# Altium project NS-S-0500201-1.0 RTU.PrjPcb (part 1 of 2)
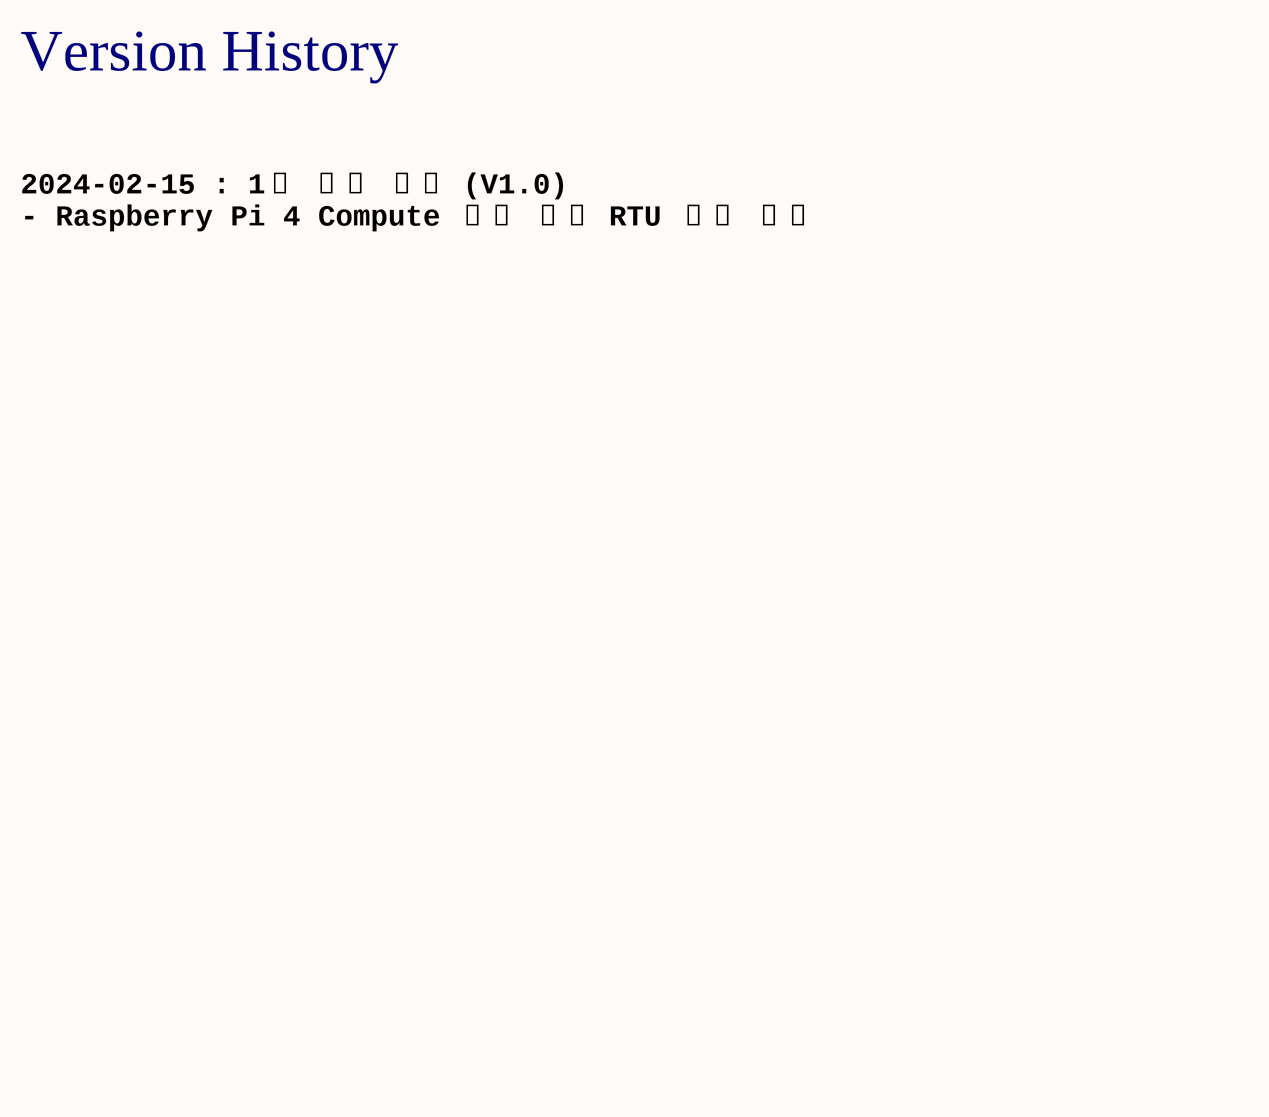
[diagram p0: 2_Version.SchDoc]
approved: 박건우(PARK K.W.); checked: 김정우(KIM J.W.); department: 전력기술팀; draw: 박진우(PARK J.W.); model: NS-S-0500201-1.0 RTU; project: Raspberry Pi 4 Compute 모듈 기반 RTU; size: A3; status: 검토중; version: 1.0
10 sheets, 268 parts. Net scope: flat (ports and power ports of the same name join across sheets).
Board file: NS-S-0500201-1.0 RTU.PcbDoc
Sheets:
  1_Cover.SchDoc
  2_Version.SchDoc
  3_Power_Boot.SchDoc
  4_CM4_CONN.SchDoc
  5_PERIPHERALS.SchDoc
  6_USB2.0.SchDoc
  7_USB3.0.SchDoc
  8_CANFD.SchDoc
  9_RS485.SchDoc
  10_HW_Component.SchDoc

## Sheet 1_Cover.SchDoc
size A3; SheetNumber: 1; SheetTotal: 9

## Sheet 2_Version.SchDoc
size A3; SheetNumber: 2; SheetTotal: 9

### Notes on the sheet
- Version History
- 2024-02-15 : 1차 회로 설계 (V1.0)
  - Raspberry Pi 4 Compute 모듈 기반 RTU 설계 초안

## Sheet 3_Power_Boot.SchDoc
size A3; SheetNumber: 3; SheetTotal: 8
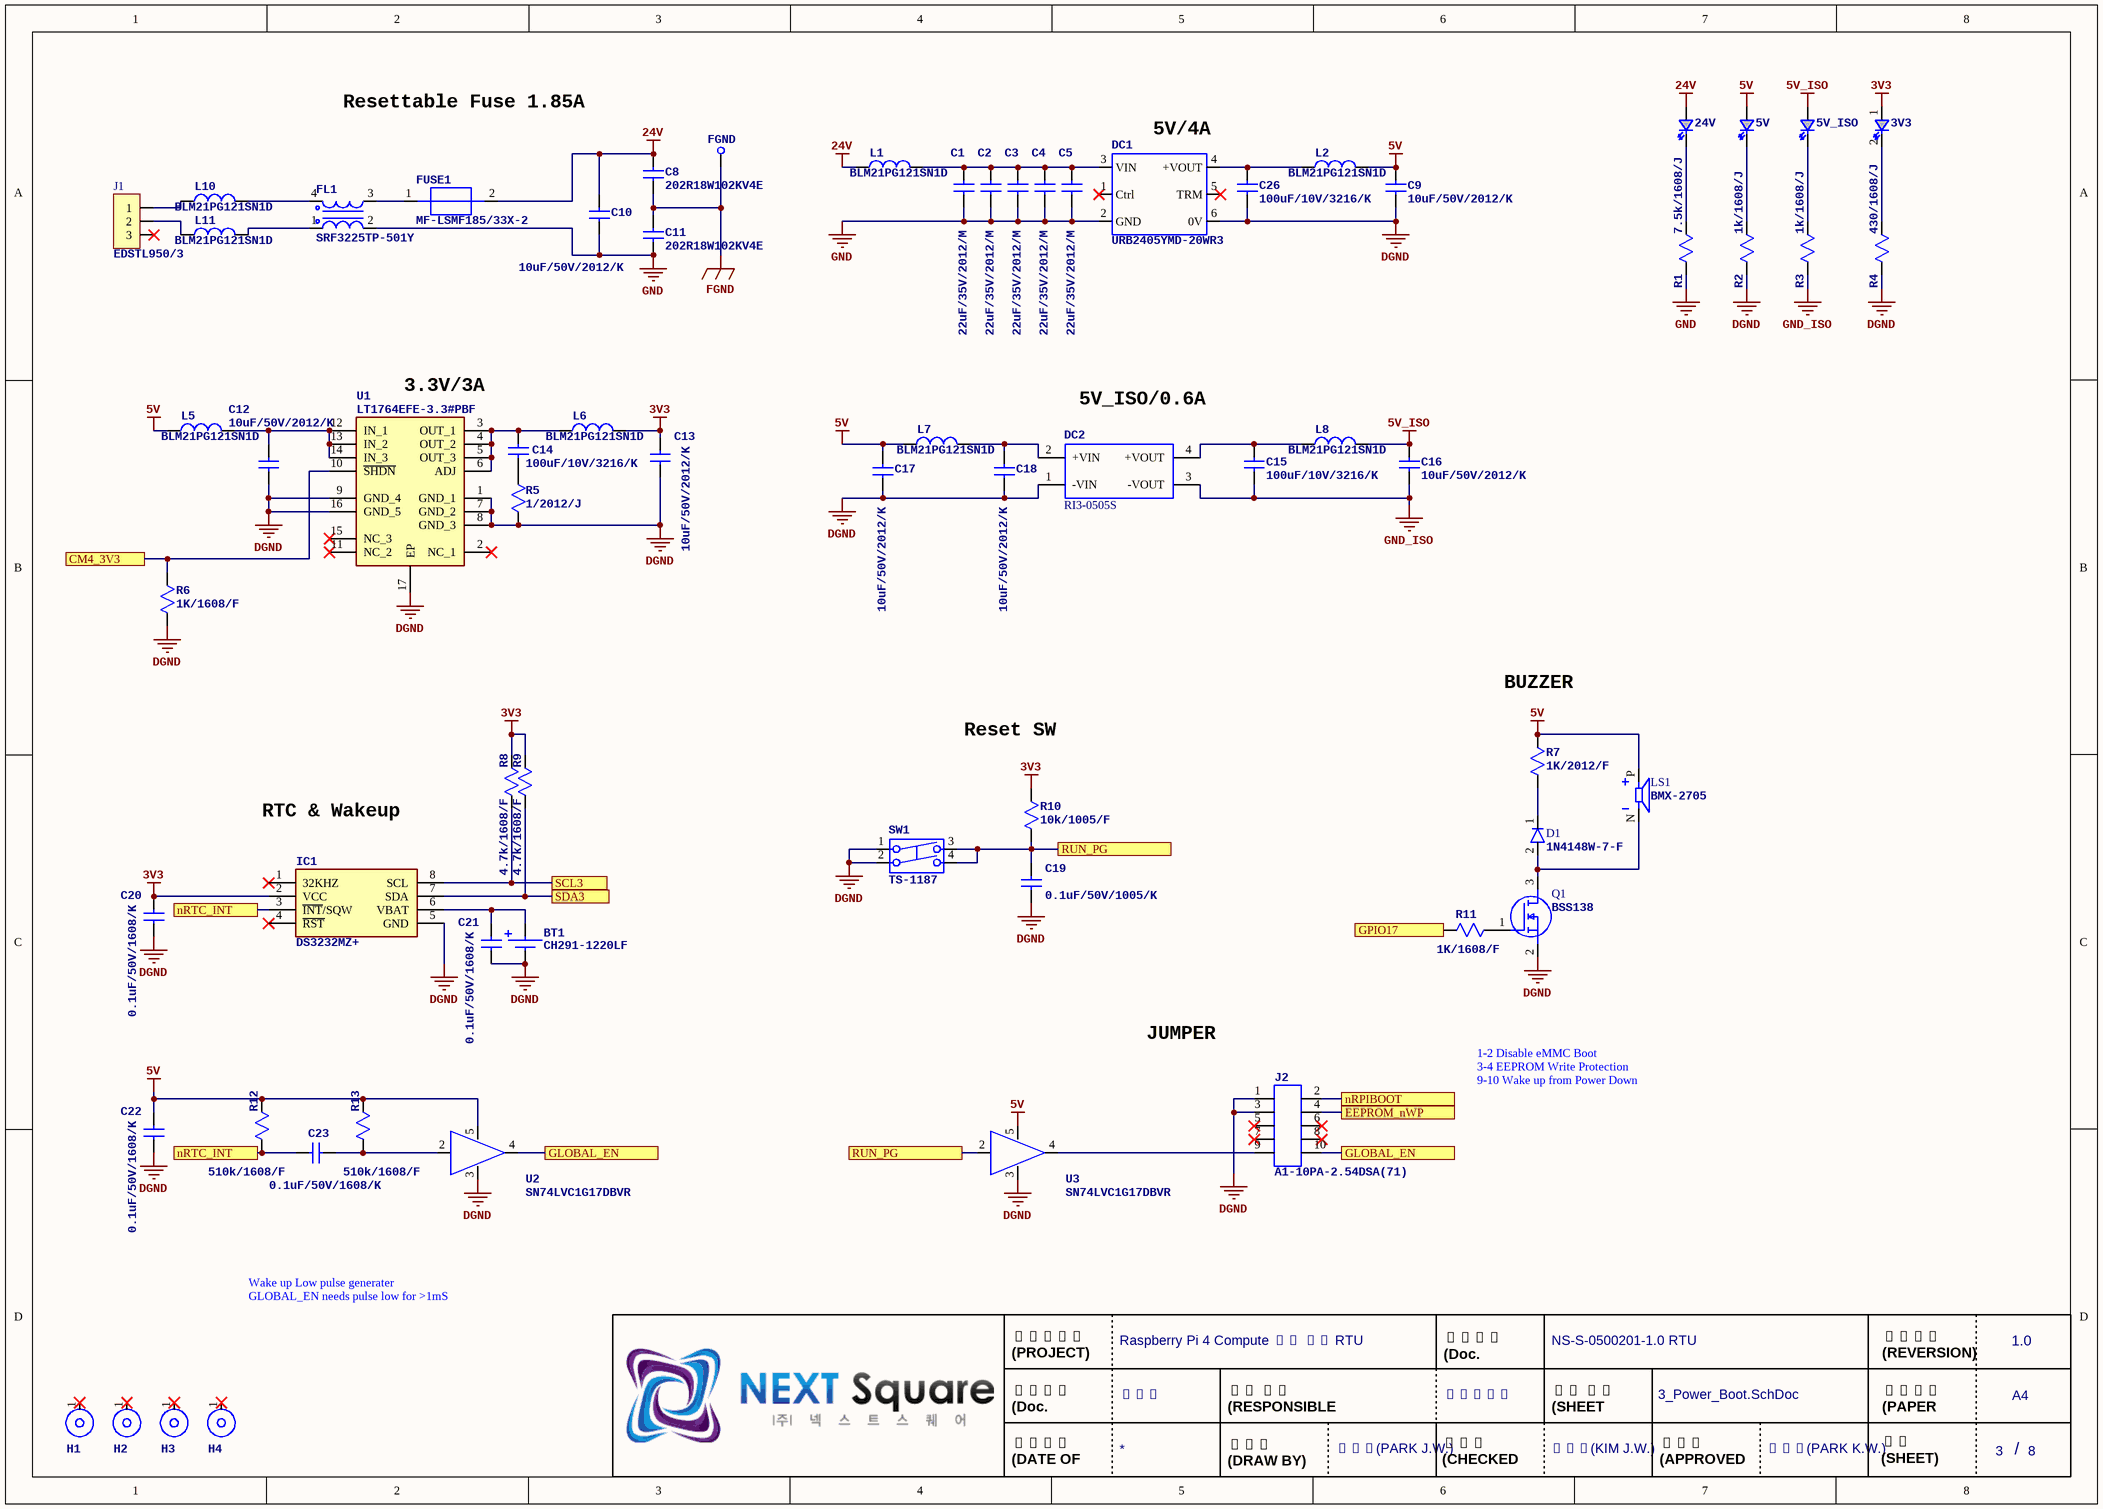
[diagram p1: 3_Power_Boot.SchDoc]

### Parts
3V3  LED Green[1608]  [LED1608]  (value not drawn)
5V  LED Green[1608]  [LED1608]  (value not drawn)
5V_ISO  LED Green[1608]  [LED1608]  (value not drawn)
24V  LED Green[1608]  [LED1608]  (value not drawn)
BT1  CH291-1220LF  [CH291-1220LF]
C1  value 22uF/35V/2012/M  [C2012]  (hidden comment: C [2012])
C2  value 22uF/35V/2012/M  [C2012]  (hidden comment: C [2012])
C3  value 22uF/35V/2012/M  [C2012]  (hidden comment: C [2012])
C4  value 22uF/35V/2012/M  [C2012]  (hidden comment: C [2012])
C5  value 22uF/35V/2012/M  [C2012]  (hidden comment: C [2012])
C8  202R18W102KV4E  [C3216]
C9  value 10uF/50V/2012/K  [C2012]  (hidden comment: C [2012])
C10  value 10uF/50V/2012/K  [C2012]  (hidden comment: C [2012])
C11  202R18W102KV4E  [C3216]
C12  value 10uF/50V/2012/K  [C2012]  (hidden comment: C [2012])
C13  value 10uF/50V/2012/K  [C2012]  (hidden comment: C [2012])
C14  value 100uF/10V/3216/K  [C3216]  (hidden comment: C [3216])
C15  value 100uF/10V/3216/K  [C3216]  (hidden comment: C [3216])
C16  value 10uF/50V/2012/K  [C2012]  (hidden comment: C [2012])
C17  value 10uF/50V/2012/K  [C2012]  (hidden comment: C [2012])
C18  value 10uF/50V/2012/K  [C2012]  (hidden comment: C [2012])
C19  value 0.1uF/50V/1005/K  [C1005]  (hidden comment: C [1005])  (no BOM)
C20  value 0.1uF/50V/1608/K  [C1608]  (hidden comment: C [1608])
C21  value 0.1uF/50V/1608/K  [C1608]  (hidden comment: C [1608])
C22  value 0.1uF/50V/1608/K  [C1608]  (hidden comment: C [1608])
C23  value 0.1uF/50V/1608/K  [C1608]  (hidden comment: C [1608])
C26  value 100uF/10V/3216/K  [C3216]  (hidden comment: C [3216])
D1  1N4148W-7-F  [SOD-123]
DC1  URB2405YMD-20WR3  [URB2405YMD-20WR3]
DC2  RI3-0505S  [RI3-0505S]
FGND  TP  [ST-1-1]  (value not drawn)
FL1  SRF3225TP-501Y  [SRF3225TP-501Y]
FUSE1  MF-LSMF185/33X-2  [MF-LSMF185_33X-2]
H1  HOLE_(3/6)  [NTH_3.6]  (value not drawn)
H2  HOLE_(3/6)  [NTH_3.6]  (value not drawn)
H3  HOLE_(3/6)  [NTH_3.6]  (value not drawn)
H4  HOLE_(3/6)  [NTH_3.6]  (value not drawn)
IC1  DS3232MZ+  [SOIC8_1.27_6.0]
J1  EDSTL950/3  [EDSTL950_3]
J2  A1-10PA-2.54DSA(71)  [A1-10PA-2.54DSA]
L1  BLM21PG121SN1D  [L2012]
L2  BLM21PG121SN1D  [L2012]
L5  BLM21PG121SN1D  [L2012]
L6  BLM21PG121SN1D  [L2012]
L7  BLM21PG121SN1D  [L2012]
L8  BLM21PG121SN1D  [L2012]
L10  BLM21PG121SN1D  [L2012]
L11  BLM21PG121SN1D  [L2012]
LS1  BMX-2705  [BUZZER-BMX-2705]
Q1  BSS138  [SOT23L]
R1  value 7.5k/1608/J  [R1608]  (hidden comment: R [1608]_J)
R2  value 1k/1608/J  [R1608]  (hidden comment: R [1608]_J)
R3  value 1k/1608/J  [R1608]  (hidden comment: R [1608]_J)
R4  value 430/1608/J  [R1608]  (hidden comment: R [1608]_J)
R5  value 1/2012/J  [R2012]  (hidden comment: R [2012]_J)
R6  value 1K/1608/F  [R1608]  (hidden comment: R [1608]_F)
R7  value 1K/2012/F  [R2012]  (hidden comment: R [2012]_F)
R8  value 4.7k/1608/F  [R1608]  (hidden comment: R [1608]_J)
R9  value 4.7k/1608/F  [R1608]  (hidden comment: R [1608]_J)
R10  value 10k/1005/F  [R1005]  (hidden comment: R [1005]_F)
R11  value 1K/1608/F  [R1608]  (hidden comment: R [1608]_F)
R12  value 510k/1608/F  [R1608]  (hidden comment: R [1608]_J)
R13  value 510k/1608/F  [R1608]  (hidden comment: R [1608]_J)
SW1  TS-1187  [TS-1187]
U1  LT1764EFE-3.3#PBF  [TSSOP16-0.65_6.5_EP]
U2  SN74LVC1G17DBVR  [SOT23_5]
U3  SN74LVC1G17DBVR  [SOT23_5]

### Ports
CM4_3V3, EEPROM_nWP, GLOBAL_EN, GPIO17, nRPIBOOT, nRTC_INT, RUN_PG, SCL3, SDA3

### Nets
3V3: 3V3.1(A) C13.1 C20.1 IC1.2(VCC) L6.2 R8.2 R9.2 R10.2
5V: 5V.1(A) C9.2 C17.2 C22.1 L2.2 L5.1 L7.1 LS1.P R7.2 R12.2 R13.2 U2.5 U3.5
5V_ISO: 5V_ISO.1(A) C16.2 L8.2
24V: 24V.1(A) C8.2 C10.1 FUSE1.2 L1.1
DGND: BT1.2 C9.1 C12.2 C13.2 C17.1 C18.1 C19.2 C20.2 C21.2 C22.2 C26.2 DC1.6(0V) DC2.1(-VIN) IC1.5(GND) J2.1 J2.3 Q1.2(S) R2.1 R4.1 R5.1 R6.1 SW1.1 SW1.2 U1.1(GND_1) U1.7(GND_2) U1.8(GND_3) U1.9(GND_4) U1.16(GND_5) U1.17(EP) U2.3 U3.3
FGND: C8.1 C11.2 FGND.1
GND: C1.2 C2.2 C3.2 C4.2 C5.2 C10.2 C11.1 DC1.2(GND) FL1.2 R1.1
GND_ISO: C15.2 C16.1 DC2.3(-VOUT) R3.1
CM4_3V3: R6.2 U1.10(~{SHDN}) ; port CM4_3V3
EEPROM_nWP: J2.4 ; port EEPROM_nWP
GLOBAL_EN: J2.10 U2.4(Y) ; port GLOBAL_EN
GPIO17: R11.2 ; port GPIO17
nRPIBOOT: J2.2 ; port nRPIBOOT
nRTC_INT: C23.1 IC1.3(~{INT}/SQW) R12.1 ; port nRTC_INT
RUN_PG: C19.1 R10.1 SW1.3 SW1.4 U3.2(A) ; port RUN_PG
SCL3: IC1.8(SCL) R8.1 ; port SCL3
SDA3: IC1.7(SDA) R9.1 ; port SDA3
Net3V3_2: 3V3.2(K) R4.2
Net5V_2: 5V.2(K) R2.2
Net5V_ISO_2: 5V_ISO.2(K) R3.2
Net24V_2: 24V.2(K) R1.2
NetBT1_1: BT1.1 C21.1 IC1.6(VBAT)
NetC1_1: C1.1 C2.1 C3.1 C4.1 C5.1 DC1.3(VIN) L1.2
NetC12_1: C12.1 L5.2 U1.12(IN_1) U1.13(IN_2) U1.14(IN_3)
NetC14_1: C14.1 L6.1 U1.3(OUT_1) U1.4(OUT_2) U1.5(OUT_3) U1.6(ADJ)
NetC14_2: C14.2 R5.2
NetC15_1: C15.1 DC2.4(+VOUT) L8.1
NetC18_2: C18.2 DC2.2(+VIN) L7.2
NetC23_2: C23.2 R13.1 U2.2(A)
NetC26_1: C26.1 DC1.4(+VOUT) L2.1
NetD1_1: D1.1 R7.1
NetD1_2: D1.2 LS1.N Q1.3(D)
NetFL1_1: FL1.1 L11.2
NetFL1_3: FL1.3 FUSE1.1
NetFL1_4: FL1.4 L10.2
NetJ1_1: J1.1 L10.1
NetJ1_2: J1.2 L11.1
NetJ2_9: J2.9 U3.4(Y)
NetQ1_1: Q1.1(G) R11.1

Not connected (* = marked no-connect by the designer): DC1 1(Ctrl)* 5(TRM)*; H1 1*; H2 1*; H3 1*; H4 1*; IC1 1(32KHZ)* 4(~{RST})*; J1 3*; J2 5* 6* 7* 8*; U1 2(NC_1)* 11(NC_2)* 15(NC_3)*; U2 1; U3 1

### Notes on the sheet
- Resettable Fuse 1.85A
- (near DC1) 5V/4A
- (near U1) 3.3V/3A
- (near DC2) 5V_ISO/0.6A
- BUZZER
- Reset SW
- RTC & Wakeup
- JUMPER
- 1-2 Disable eMMC Boot
  3-4 EEPROM Write Protection
  9-10 Wake up from Power Down
- Wake up Low pulse generater
  GLOBAL_EN needs pulse low for >1mS

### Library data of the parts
3V3 5V 5V_ISO 24V = LED Green[1608]: Standard LEDs - SMD SMD 1608(mm) GREEN
BT1 = CH291-1220LF: Battery Holder (CR1220 Need); Maker: Multicomp
C1-C5 = C [2012]: MLCC - SMD/SMT 35V X5R +/-20% 2012(mm)
C8 C11 = 202R18W102KV4E: Multilayer Ceramic Capacitors MLCC - SMD/SMT 2Kvolts 1000pF 10% X7R; Value: 2000V/1000pF
C9 C10 C12 C13 C16-C18 = C [2012]: MLCC - SMD/SMT 50V X5R +/-10% 2012(mm)
C14 C15 C26 = C [3216]_10V: MLCC - SMD/SMT 10V X5R +/-10% 3216(mm)
C19 = C [1005]: MLCC - SMD/SMT 50V X5R +/-10% 1005(mm)
C20-C23 = C [1608]: MLCC - SMD/SMT 50V X5R +/-10% 1608(mm)
D1 = 1N4148W-7-F: Diodes - General Purpose, Power, Switching SURFACE MOUNT FAST SWITCHING DIODE; Manufacturer_Name: Diodes Inc.; Maker: Diodes Incorporated
DC1 = URB2405YMD-20WR3: 20W isolated DC-DC converter DIP package, Ultra-wide input and regulated single output; Maker: MORNSUN
DC2 = RI3-0505S: Isolated Module DC DC Converter 1 Output 5V 600mA 4.5V - 5.5V Input; Maker: RECOM Power
FGND = TP: TEST POINT 1PI
FL1 = SRF3225TP-501Y: CMC,filter , 3.2x2.5x2.2mm,500ohm+/-25%,2A,shd
FUSE1 = MF-LSMF185/33X-2: Resettable Fuses - PPTC PTC RESETTABLE 1.85A 33V SMD 2920; Maker: Bourns
H1-H4 = HOLE_(3/6): HOLE
IC1 = DS3232MZ+: DS3232M Series 4.5 V ±5 ppm Surface Mount I2C Real-Time Clock - SOIC-8; Manufacturer_Name: Maxim Integrated; Manufacturer: Maxim; Memory Size: 236B; Time Format: HH:MM:SS (12/24 hr); Max Supply Voltage: 4.5V; Min Supply Voltage: 2.3V; Interface: I2C,Serial,2-Wire; Date Format: YY-MM-DD-dd
J1 = EDSTL950/3: Connector
J2 = A1-10PA-2.54DSA(71): Headers & Wire Housings 10P M PIN HEADER DR STRAIGHT TYPE GOLD; Maker: Hirose
L1 L2 L5-L8 L10 L11 = BLM21PG121SN1D: Ferrite Beads Multi-Layer 120Ohm 25% 100MHz 3A 30mOhm DCR 0805 Paper T/R; Maker: MURATA; Material: Steel,Ferrite; Impedance: 120R; DC Resistance (DCR): 30mR; Number of Lines: 1
LS1 = BMX-2705: 9 mm, 5 Vdc, 90 dB, SMD Passive, Magnetic Audio Indicator Buzzer; Maker: KANGSEO EST
Q1 = BSS138: MOSFET (N-Channel); Manufacturer_Name: ON Semiconductor
R1-R4 R8 R9 R12 R13 = R [1608]_J: SMD  Chip Resistor +/-5% 1608(mm)
R5 = R [2012]_J: SMD  Chip Resistor +/-5% 2012(mm)
R6 R11 = R [1608]_F: SMD  Chip Resistor +/-1% 1608(mm)
R7 = R [2012]_F: SMD  Chip Resistor +/-1% 2012(mm)
R10 = R [1005]_F: SMD  Chip Resistor +/-1% 1005(mm)
SW1 = TS-1187: SMD type SWITCH; Maker: SY Hitech
U1 = LT1764EFE-3.3#PBF: LDO Regulator Pos 3.3V 3A 16-Pin TSSOP EP; Manufacturer_Name: Analog Devices; Manufacturer: Analog Devices / Linear Technology; Dropout Voltage: 340mV; Number of Regulators: 1; Min Current Limit: 3.1A; Value: 3.3V/3A
U2 U3 = SN74LVC1G17DBVR: Buffers & Line Drivers Single Schmitt-Trgr; Maker: TI

## Sheet 4_CM4_CONN.SchDoc
size A3; SheetNumber: 4; SheetTotal: 9
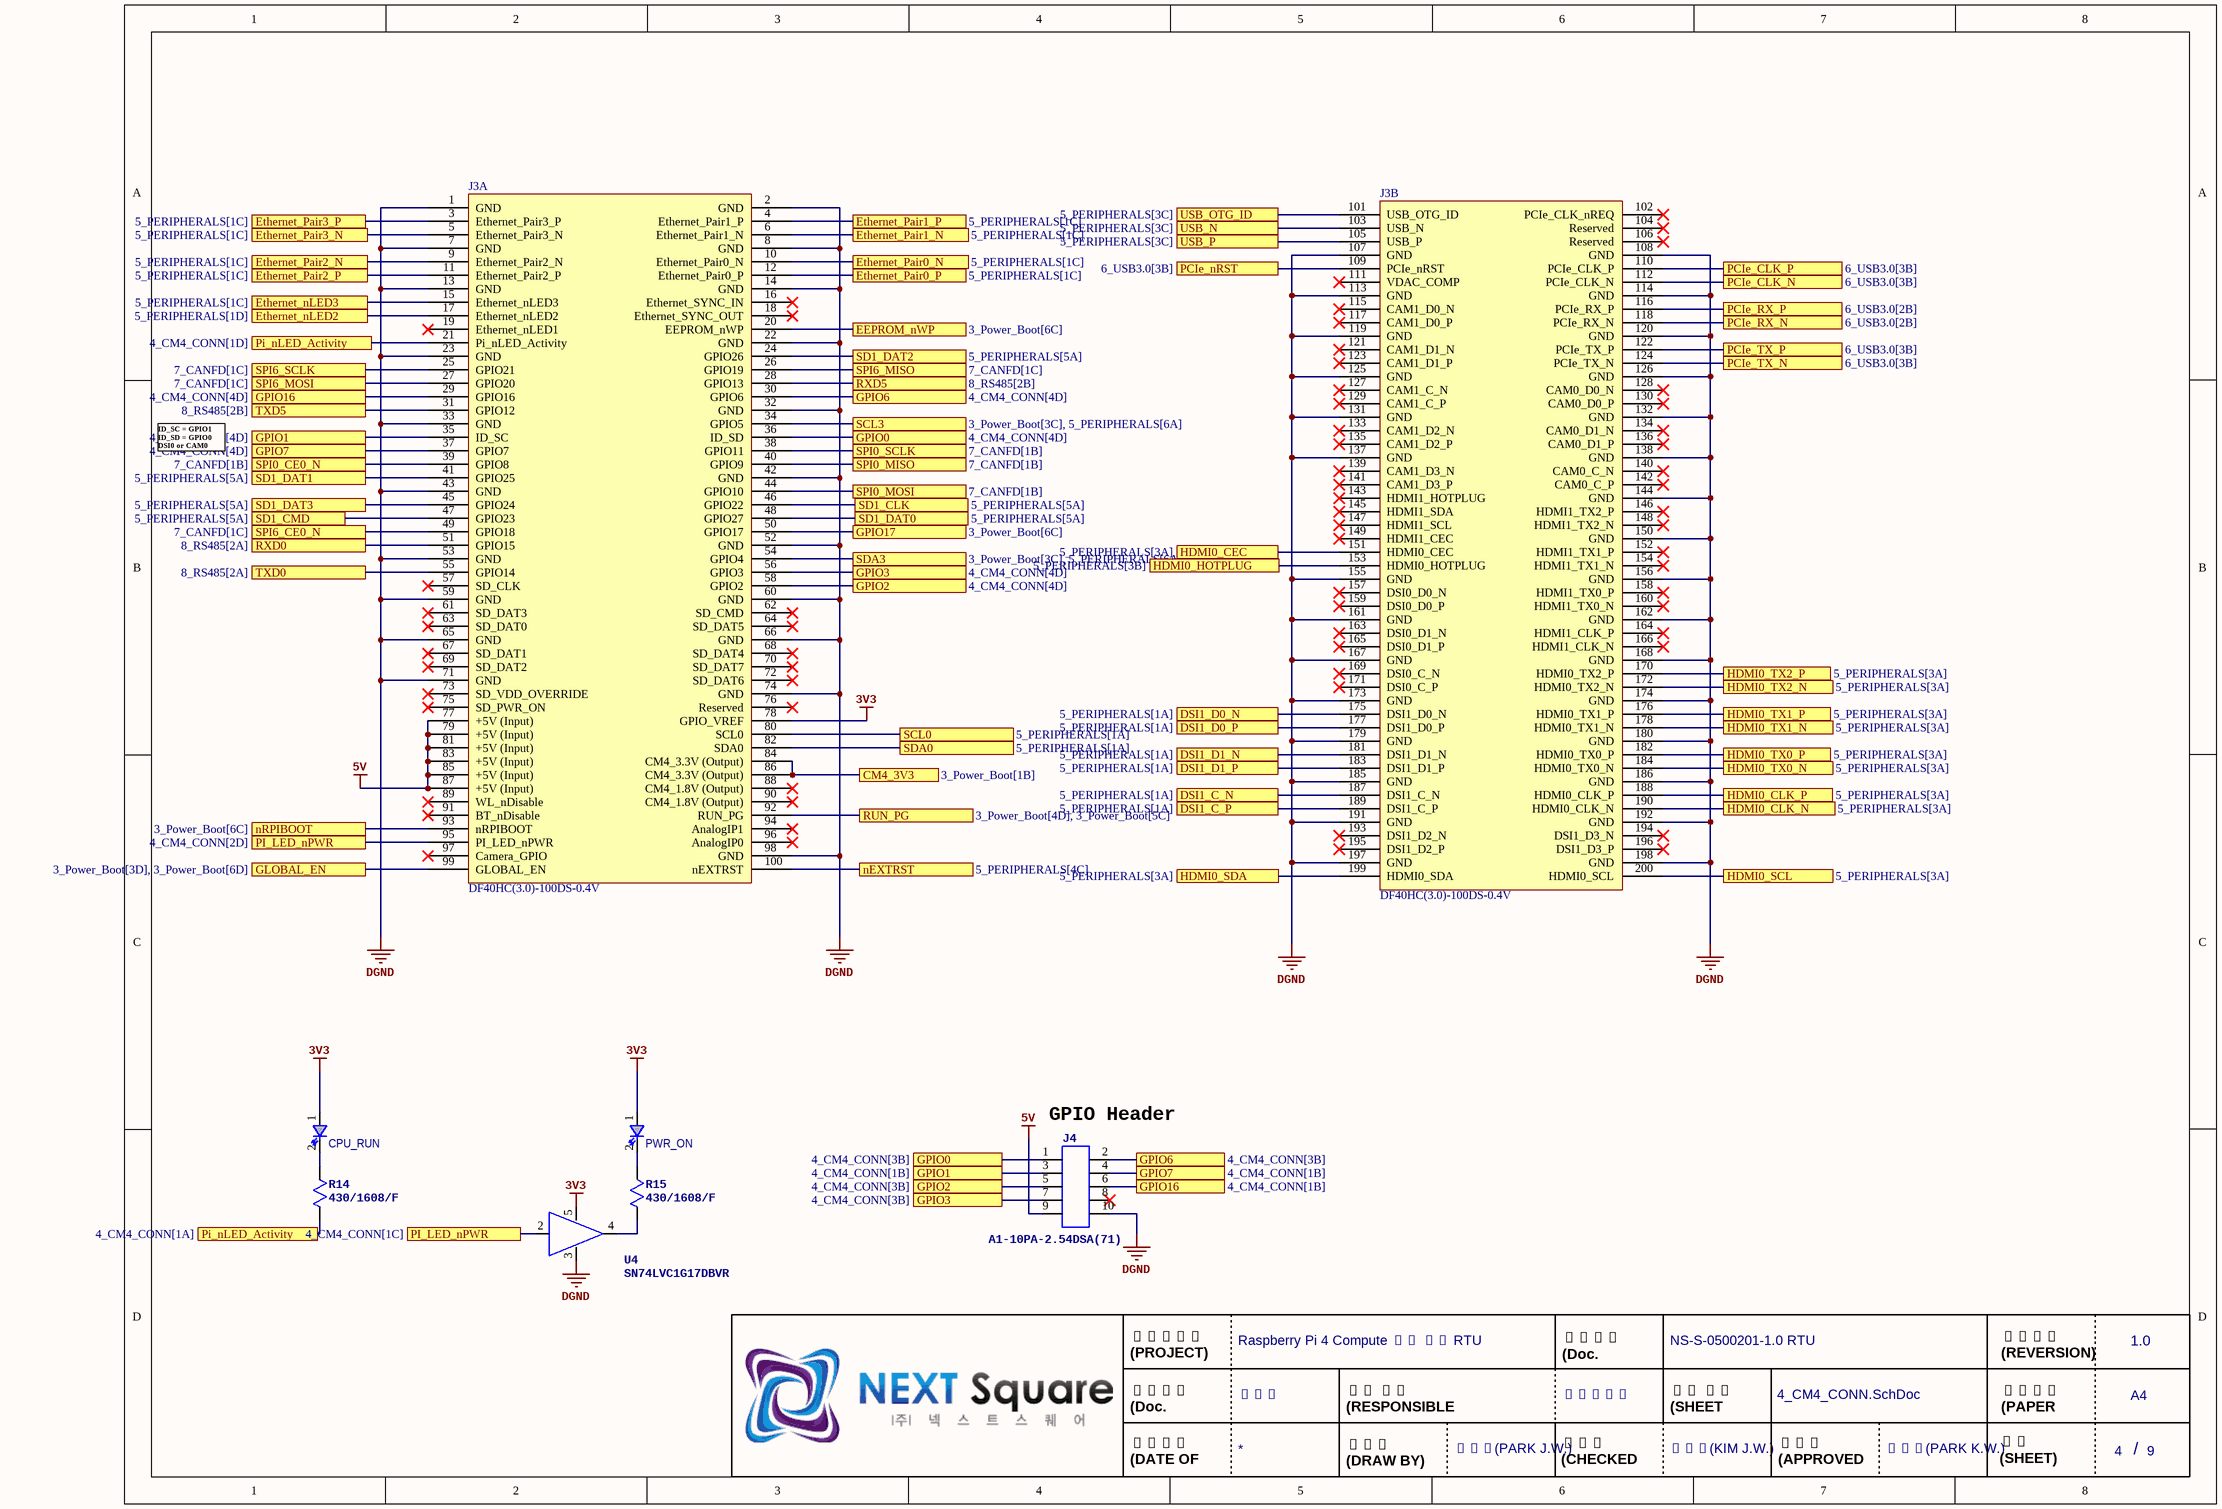
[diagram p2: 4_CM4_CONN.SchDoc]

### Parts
CPU_RUN  LED Green[1608]  [LED1608]  (value not drawn)
J3  DF40HC(3.0)-100DS-0.4V  [DF40HC(3.0)-100DS-0.4V]  (parts A,B of 2)
J4  A1-10PA-2.54DSA(71)  [A1-10PA-2.54DSA]
PWR_ON  LED Green[1608]  [LED1608]  (value not drawn)
R14  value 430/1608/F  [R1608]  (hidden comment: R [1608]_J)
R15  value 430/1608/F  [R1608]  (hidden comment: R [1608]_J)
U4  SN74LVC1G17DBVR  [SOT23_5]

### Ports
CM4_3V3 (see 3_Power_Boot[1B]), DSI1_C_N (see 5_PERIPHERALS[1A]), DSI1_C_P (see 5_PERIPHERALS[1A]), DSI1_D0_N (see 5_PERIPHERALS[1A]), DSI1_D0_P (see 5_PERIPHERALS[1A]), DSI1_D1_N (see 5_PERIPHERALS[1A]), DSI1_D1_P (see 5_PERIPHERALS[1A]), EEPROM_nWP (see 3_Power_Boot[6C]), Ethernet_nLED2 (see 5_PERIPHERALS[1D]), Ethernet_nLED3 (see 5_PERIPHERALS[1C]), Ethernet_Pair0_N (see 5_PERIPHERALS[1C]), Ethernet_Pair0_P (see 5_PERIPHERALS[1C]), Ethernet_Pair1_N (see 5_PERIPHERALS[1C]), Ethernet_Pair1_P (see 5_PERIPHERALS[1C]), Ethernet_Pair2_N (see 5_PERIPHERALS[1C]), Ethernet_Pair2_P (see 5_PERIPHERALS[1C]), Ethernet_Pair3_N (see 5_PERIPHERALS[1C]), Ethernet_Pair3_P (see 5_PERIPHERALS[1C]), GLOBAL_EN (see 3_Power_Boot[3D], 3_Power_Boot[6D]), GPIO0 (see 4_CM4_CONN[3B]), GPIO0 (see 4_CM4_CONN[4D]), GPIO1 (see 4_CM4_CONN[1B]), GPIO1 (see 4_CM4_CONN[4D]), GPIO2 (see 4_CM4_CONN[3B]), GPIO2 (see 4_CM4_CONN[4D]), GPIO3 (see 4_CM4_CONN[3B]), GPIO3 (see 4_CM4_CONN[4D]), GPIO6 (see 4_CM4_CONN[3B]), GPIO6 (see 4_CM4_CONN[4D]), GPIO7 (see 4_CM4_CONN[1B]), GPIO7 (see 4_CM4_CONN[4D]), GPIO16 (see 4_CM4_CONN[1B]), GPIO16 (see 4_CM4_CONN[4D]), GPIO17 (see 3_Power_Boot[6C]), HDMI0_CEC (see 5_PERIPHERALS[3A]), HDMI0_CLK_N (see 5_PERIPHERALS[3A]), HDMI0_CLK_P (see 5_PERIPHERALS[3A]), HDMI0_HOTPLUG (see 5_PERIPHERALS[3B]), HDMI0_SCL (see 5_PERIPHERALS[3A]), HDMI0_SDA (see 5_PERIPHERALS[3A]), HDMI0_TX0_N (see 5_PERIPHERALS[3A]), HDMI0_TX0_P (see 5_PERIPHERALS[3A]), HDMI0_TX1_N (see 5_PERIPHERALS[3A]), HDMI0_TX1_P (see 5_PERIPHERALS[3A]), HDMI0_TX2_N (see 5_PERIPHERALS[3A]), HDMI0_TX2_P (see 5_PERIPHERALS[3A]), nEXTRST (see 5_PERIPHERALS[4C]), nRPIBOOT (see 3_Power_Boot[6C]), PCIe_CLK_N (see 6_USB3.0[3B]), PCIe_CLK_P (see 6_USB3.0[3B]), PCIe_nRST (see 6_USB3.0[3B]), PCIe_RX_N (see 6_USB3.0[2B]), PCIe_RX_P (see 6_USB3.0[2B]), PCIe_TX_N (see 6_USB3.0[3B]), PCIe_TX_P (see 6_USB3.0[3B]), PI_LED_nPWR (see 4_CM4_CONN[1C]), PI_LED_nPWR (see 4_CM4_CONN[2D]), Pi_nLED_Activity (see 4_CM4_CONN[1A]), Pi_nLED_Activity (see 4_CM4_CONN[1D]), RUN_PG (see 3_Power_Boot[4D], 3_Power_Boot[5C]), RXD0 (see 8_RS485[2A]), RXD5 (see 8_RS485[2B]), SCL0 (see 5_PERIPHERALS[1A]), SCL3 (see 3_Power_Boot[3C], 5_PERIPHERALS[6A]), SD1_CLK (see 5_PERIPHERALS[5A]), SD1_CMD (see 5_PERIPHERALS[5A]), SD1_DAT0 (see 5_PERIPHERALS[5A]), SD1_DAT1 (see 5_PERIPHERALS[5A]), SD1_DAT2 (see 5_PERIPHERALS[5A]), SD1_DAT3 (see 5_PERIPHERALS[5A]), SDA0 (see 5_PERIPHERALS[1A]), SDA3 (see 3_Power_Boot[3C], 5_PERIPHERALS[6A]), SPI0_CE0_N (see 7_CANFD[1B]), SPI0_MISO (see 7_CANFD[1B]), SPI0_MOSI (see 7_CANFD[1B]), SPI0_SCLK (see 7_CANFD[1B]), SPI6_CE0_N (see 7_CANFD[1C]), SPI6_MISO (see 7_CANFD[1C]), SPI6_MOSI (see 7_CANFD[1C]), SPI6_SCLK (see 7_CANFD[1C]), TXD0 (see 8_RS485[2A]), TXD5 (see 8_RS485[2B]), USB_N (see 5_PERIPHERALS[3C]), USB_OTG_ID (see 5_PERIPHERALS[3C]), USB_P (see 5_PERIPHERALS[3C])

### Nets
3V3: CPU_RUN.1(A) J3.78(GPIO_VREF) PWR_ON.1(A) U4.5
5V: J3.77(+5V_(Input)) J3.79(+5V_(Input)) J3.81(+5V_(Input)) J3.83(+5V_(Input)) J3.85(+5V_(Input)) J3.87(+5V_(Input)) J4.9
DGND: J3.1(GND) J3.2(GND) J3.7(GND) J3.8(GND) J3.13(GND) J3.14(GND) J3.22(GND) J3.23(GND) J3.32(GND) J3.33(GND) J3.42(GND) J3.43(GND) J3.52(GND) J3.53(GND) J3.59(GND) J3.60(GND) J3.65(GND) J3.66(GND) J3.71(GND) J3.74(GND) J3.98(GND) J3.107(GND) J3.108(GND) J3.113(GND) J3.114(GND) J3.119(GND) J3.120(GND) J3.125(GND) J3.126(GND) J3.131(GND) J3.132(GND) J3.137(GND) J3.138(GND) J3.144(GND) J3.150(GND) J3.155(GND) J3.156(GND) J3.161(GND) J3.162(GND) J3.167(GND) J3.168(GND) J3.173(GND) J3.174(GND) J3.179(GND) J3.180(GND) J3.185(GND) J3.186(GND) J3.191(GND) J3.192(GND) J3.197(GND) J3.198(GND) J4.10 U4.3
CM4_3V3: J3.84(CM4_3.3V_(Output)) J3.86(CM4_3.3V_(Output)) ; port CM4_3V3
DSI1_C_N: J3.187(DSI1_C_N) ; port DSI1_C_N
DSI1_C_P: J3.189(DSI1_C_P) ; port DSI1_C_P
DSI1_D0_N: J3.175(DSI1_D0_N) ; port DSI1_D0_N
DSI1_D0_P: J3.177(DSI1_D0_P) ; port DSI1_D0_P
DSI1_D1_N: J3.181(DSI1_D1_N) ; port DSI1_D1_N
DSI1_D1_P: J3.183(DSI1_D1_P) ; port DSI1_D1_P
EEPROM_nWP: J3.20(EEPROM_nWP) ; port EEPROM_nWP
Ethernet_nLED2: J3.17(Ethernet_nLED2) ; port Ethernet_nLED2
Ethernet_nLED3: J3.15(Ethernet_nLED3) ; port Ethernet_nLED3
Ethernet_Pair0_N: J3.10(Ethernet_Pair0_N) ; port Ethernet_Pair0_N
Ethernet_Pair0_P: J3.12(Ethernet_Pair0_P) ; port Ethernet_Pair0_P
Ethernet_Pair1_N: J3.6(Ethernet_Pair1_N) ; port Ethernet_Pair1_N
Ethernet_Pair1_P: J3.4(Ethernet_Pair1_P) ; port Ethernet_Pair1_P
Ethernet_Pair2_N: J3.9(Ethernet_Pair2_N) ; port Ethernet_Pair2_N
Ethernet_Pair2_P: J3.11(Ethernet_Pair2_P) ; port Ethernet_Pair2_P
Ethernet_Pair3_N: J3.5(Ethernet_Pair3_N) ; port Ethernet_Pair3_N
Ethernet_Pair3_P: J3.3(Ethernet_Pair3_P) ; port Ethernet_Pair3_P
GLOBAL_EN: J3.99(GLOBAL_EN) ; port GLOBAL_EN
GPIO0: J3.36(ID_SD) J4.1 ; port GPIO0
GPIO1: J3.35(ID_SC) J4.3 ; port GPIO1
GPIO2: J3.58(GPIO2) J4.5 ; port GPIO2
GPIO3: J3.56(GPIO3) J4.7 ; port GPIO3
GPIO6: J3.30(GPIO6) J4.2 ; port GPIO6
GPIO7: J3.37(GPIO7) J4.4 ; port GPIO7
GPIO16: J3.29(GPIO16) J4.6 ; port GPIO16
GPIO17: J3.50(GPIO17) ; port GPIO17
HDMI0_CEC: J3.151(HDMI0_CEC) ; port HDMI0_CEC
HDMI0_CLK_N: J3.190(HDMI0_CLK_N) ; port HDMI0_CLK_N
HDMI0_CLK_P: J3.188(HDMI0_CLK_P) ; port HDMI0_CLK_P
HDMI0_HOTPLUG: J3.153(HDMI0_HOTPLUG) ; port HDMI0_HOTPLUG
HDMI0_SCL: J3.200(HDMI0_SCL) ; port HDMI0_SCL
HDMI0_SDA: J3.199(HDMI0_SDA) ; port HDMI0_SDA
HDMI0_TX0_N: J3.184(HDMI0_TX0_N) ; port HDMI0_TX0_N
HDMI0_TX0_P: J3.182(HDMI0_TX0_P) ; port HDMI0_TX0_P
HDMI0_TX1_N: J3.178(HDMI0_TX1_N) ; port HDMI0_TX1_N
HDMI0_TX1_P: J3.176(HDMI0_TX1_P) ; port HDMI0_TX1_P
HDMI0_TX2_N: J3.172(HDMI0_TX2_N) ; port HDMI0_TX2_N
HDMI0_TX2_P: J3.170(HDMI0_TX2_P) ; port HDMI0_TX2_P
nEXTRST: J3.100(nEXTRST) ; port nEXTRST
nRPIBOOT: J3.93(nRPIBOOT) ; port nRPIBOOT
PCIe_CLK_N: J3.112(PCIe_CLK_N) ; port PCIe_CLK_N
PCIe_CLK_P: J3.110(PCIe_CLK_P) ; port PCIe_CLK_P
PCIe_nRST: J3.109(PCIe_nRST) ; port PCIe_nRST
PCIe_RX_N: J3.118(PCIe_RX_N) ; port PCIe_RX_N
PCIe_RX_P: J3.116(PCIe_RX_P) ; port PCIe_RX_P
PCIe_TX_N: J3.124(PCIe_TX_N) ; port PCIe_TX_N
PCIe_TX_P: J3.122(PCIe_TX_P) ; port PCIe_TX_P
PI_LED_nPWR: J3.95(PI_LED_nPWR) U4.2(A) ; port PI_LED_nPWR
Pi_nLED_Activity: J3.21(Pi_nLED_Activity) R14.1 ; port Pi_nLED_Activity
RUN_PG: J3.92(RUN_PG) ; port RUN_PG
RXD0: J3.51(GPIO15) ; port RXD0
RXD5: J3.28(GPIO13) ; port RXD5
SCL0: J3.80(SCL0) ; port SCL0
SCL3: J3.34(GPIO5) ; port SCL3
SD1_CLK: J3.46(GPIO22) ; port SD1_CLK
SD1_CMD: J3.47(GPIO23) ; port SD1_CMD
SD1_DAT0: J3.48(GPIO27) ; port SD1_DAT0
SD1_DAT1: J3.41(GPIO25) ; port SD1_DAT1
SD1_DAT2: J3.24(GPIO26) ; port SD1_DAT2
SD1_DAT3: J3.45(GPIO24) ; port SD1_DAT3
SDA0: J3.82(SDA0) ; port SDA0
SDA3: J3.54(GPIO4) ; port SDA3
SPI0_CE0_N: J3.39(GPIO8) ; port SPI0_CE0_N
SPI0_MISO: J3.40(GPIO9) ; port SPI0_MISO
SPI0_MOSI: J3.44(GPIO10) ; port SPI0_MOSI
SPI0_SCLK: J3.38(GPIO11) ; port SPI0_SCLK
SPI6_CE0_N: J3.49(GPIO18) ; port SPI6_CE0_N
SPI6_MISO: J3.26(GPIO19) ; port SPI6_MISO
SPI6_MOSI: J3.27(GPIO20) ; port SPI6_MOSI
SPI6_SCLK: J3.25(GPIO21) ; port SPI6_SCLK
TXD0: J3.55(GPIO14) ; port TXD0
TXD5: J3.31(GPIO12) ; port TXD5
USB_N: J3.103(USB_N) ; port USB_N
USB_OTG_ID: J3.101(USB_OTG_ID) ; port USB_OTG_ID
USB_P: J3.105(USB_P) ; port USB_P
NetCPU_RUN_2: CPU_RUN.2(K) R14.2
NetPWR_ON_2: PWR_ON.2(K) R15.2
NetR15_1: R15.1 U4.4(Y)

Not connected (* = marked no-connect by the designer): J3 16(Ethernet_SYNC_IN)* 18(Ethernet_SYNC_OUT)* 19(Ethernet_nLED1)* 57(SD_CLK)* 61(SD_DAT3)* 62(SD_CMD)* 63(SD_DAT0)* 64(SD_DAT5)* 67(SD_DAT1)* 68(SD_DAT4)* 69(SD_DAT2)* 70(SD_DAT7)* 72(SD_DAT6)* 73(SD_VDD_OVERRIDE)* 75(SD_PWR_ON)* 76(Reserved)* 88(CM4_1.8V_(Output))* 89(WL_nDisable)* 90(CM4_1.8V_(Output))* 91(BT_nDisable)* 94(AnalogIP1)* 96(AnalogIP0)* 97(Camera_GPIO)* 102(PCIe_CLK_nREQ)* 104(Reserved)* 106(Reserved)* 111(VDAC_COMP)* 115(CAM1_D0_N)* 117(CAM1_D0_P)* 121(CAM1_D1_N)* 123(CAM1_D1_P)* 127(CAM1_C_N)* 128(CAM0_D0_N)* 129(CAM1_C_P)* 130(CAM0_D0_P)* 133(CAM1_D2_N)* 134(CAM0_D1_N)* 135(CAM1_D2_P)* 136(CAM0_D1_P)* 139(CAM1_D3_N)* 140(CAM0_C_N)* 141(CAM1_D3_P)* 142(CAM0_C_P)* 143(HDMI1_HOTPLUG)* 145(HDMI1_SDA)* 146(HDMI1_TX2_P)* 147(HDMI1_SCL)* 148(HDMI1_TX2_N)* 149(HDMI1_CEC)* 152(HDMI1_TX1_P)* 154(HDMI1_TX1_N)* 157(DSI0_D0_N)* 158(HDMI1_TX0_P)* 159(DSI0_D0_P)* 160(HDMI1_TX0_N)* 163(DSI0_D1_N)* 164(HDMI1_CLK_P)* 165(DSI0_D1_P)* 166(HDMI1_CLK_N)* 169(DSI0_C_N)* 171(DSI0_C_P)* 193(DSI1_D2_N)* 194(DSI1_D3_N)* 195(DSI1_D2_P)* 196(DSI1_D3_P)*; J4 8*; U4 1

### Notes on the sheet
- ID_SC = GPIO1
  ID_SD = GPIO0
  DSI0 or CAM0
- (near J4) GPIO Header

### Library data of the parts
CPU_RUN PWR_ON = LED Green[1608]: Standard LEDs - SMD SMD 1608(mm) GREEN
J3 = DF40HC(3.0)-100DS-0.4V: Board to Board & Mezzanine Connectors 100P 2R 3MM RECPT SMT VERT 0.4MM PITCH; Maker: Hirose
J4 = A1-10PA-2.54DSA(71): as J2 on sheet 3_Power_Boot
R14 R15 = R [1608]_J: SMD  Chip Resistor +/-5% 1608(mm)
U4 = SN74LVC1G17DBVR: as U2 on sheet 3_Power_Boot

## Sheet 5_PERIPHERALS.SchDoc
size A3; SheetNumber: 5; SheetTotal: 9; Organization: Altium Limited; Address1: L3, 12a Rodborough Rd; Address2: Frenchs Forest; Address3: NSW; Address4: Australia 2086
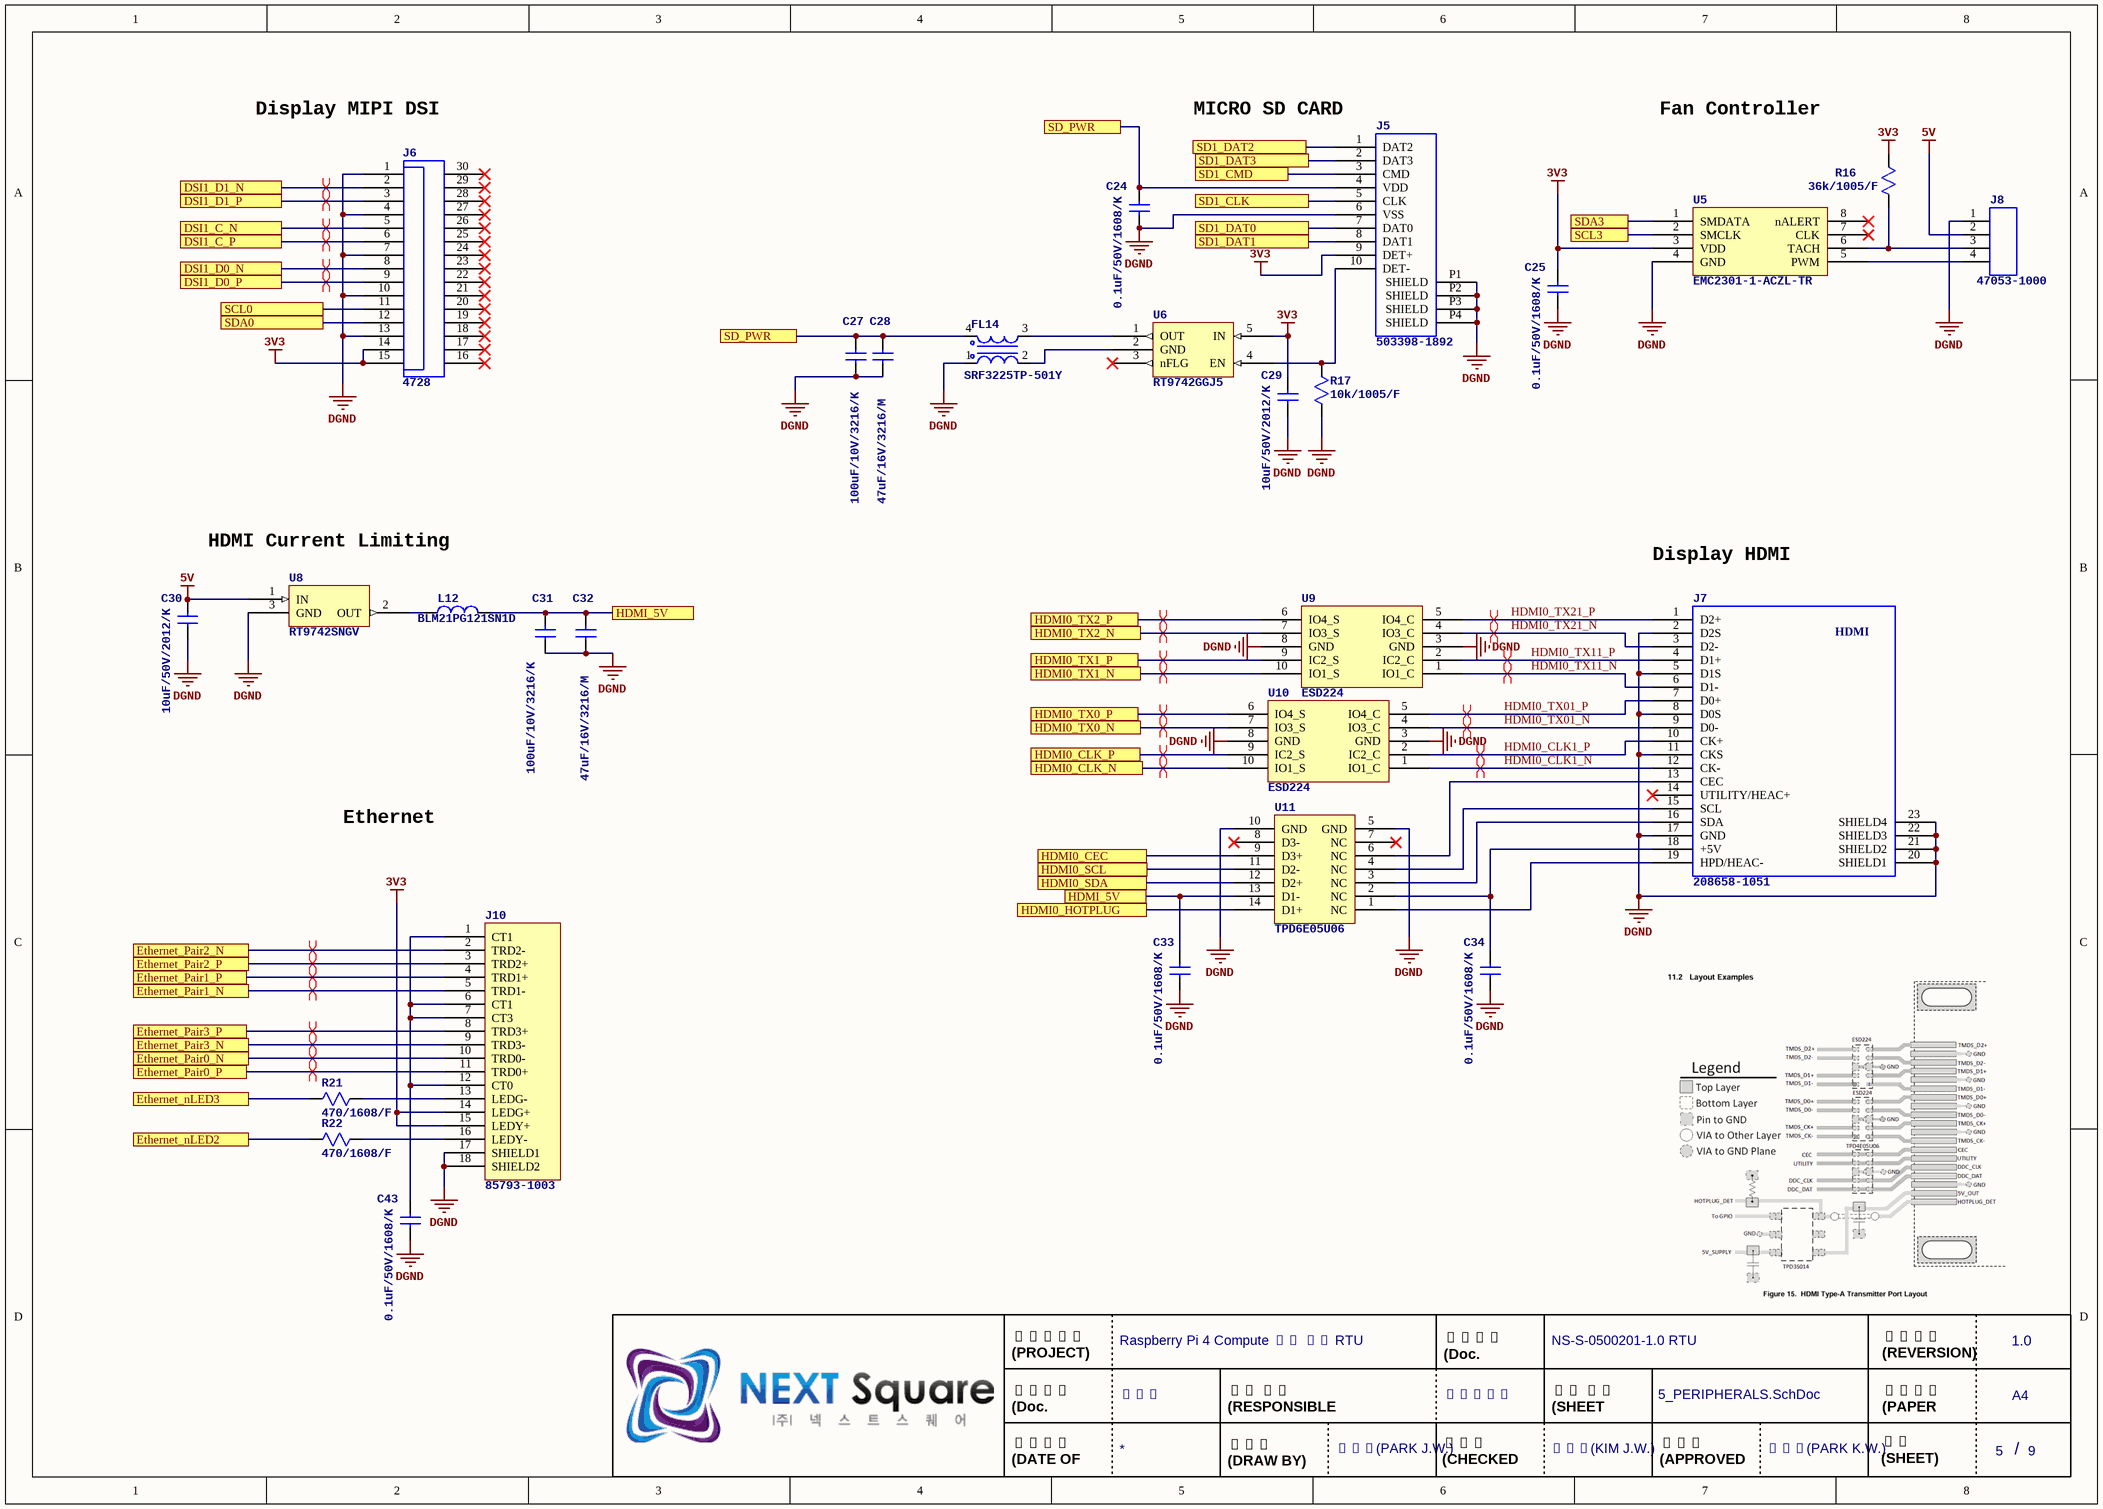
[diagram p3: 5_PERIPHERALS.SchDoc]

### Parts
C24  value 0.1uF/50V/1608/K  [C1608]  (hidden comment: C [1608])
C25  value 0.1uF/50V/1608/K  [C1608]  (hidden comment: C [1608])
C27  value 100uF/10V/3216/K  [C3216]  (hidden comment: C [3216])
C28  value 47uF/16V/3216/M  [C3216]  (hidden comment: C [3216])
C29  value 10uF/50V/2012/K  [C2012]  (hidden comment: C [2012])
C30  value 10uF/50V/2012/K  [C2012]  (hidden comment: C [2012])
C31  value 100uF/10V/3216/K  [C3216]  (hidden comment: C [3216])
C32  value 47uF/16V/3216/M  [C3216]  (hidden comment: C [3216])
C33  value 0.1uF/50V/1608/K  [C1608]  (hidden comment: C [1608])
C34  value 0.1uF/50V/1608/K  [C1608]  (hidden comment: C [1608])
C43  value 0.1uF/50V/1608/K  [C1608]  (hidden comment: C [1608])
FL14  SRF3225TP-501Y  [SRF3225TP-501Y]
J5  503398-1892  [MOLEX_503398-1892]
J6  4728  [4728]
J7  208658-1051  [MOLEX_208658-1051]
J8  47053-1000  [47053-1000]
J10  85793-1003  [MOLEX_85793-1003]
L12  BLM21PG121SN1D  [L2012]
R16  value 36k/1005/F  [R1005]  (hidden comment: R [1005]_F)
R17  value 10k/1005/F  [R1005]  (hidden comment: R [1005]_F)
R21  value 470/1608/F  [R1608]  (hidden comment: R [1608]_J)
R22  value 470/1608/F  [R1608]  (hidden comment: R [1608]_J)
U5  EMC2301-1-ACZL-TR  [MSOP8_0.65_5.0]
U6  RT9742GGJ5  [SOT23_5]
U8  RT9742SNGV  [SOT23L]
U9  ESD224  [USON10_0.5_1.1X2.6]
U10  ESD224  [USON10_0.5_1.1X2.6]
U11  TPD6E05U06  [USON14_0.5_1.35X3.5]

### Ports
DSI1_C_N, DSI1_C_P, DSI1_D0_N, DSI1_D0_P, DSI1_D1_N, DSI1_D1_P, Ethernet_nLED2, Ethernet_nLED3, Ethernet_Pair0_N, Ethernet_Pair0_P, Ethernet_Pair1_N, Ethernet_Pair1_P, Ethernet_Pair2_N, Ethernet_Pair2_P, Ethernet_Pair3_N, Ethernet_Pair3_P, HDMI0_CEC, HDMI0_CLK_N, HDMI0_CLK_P, HDMI0_HOTPLUG, HDMI0_SCL, HDMI0_SDA, HDMI0_TX0_N, HDMI0_TX0_P, HDMI0_TX1_N, HDMI0_TX1_P, HDMI0_TX2_N, HDMI0_TX2_P, HDMI_5V, SCL0, SCL3, SD1_CLK, SD1_CMD, SD1_DAT0, SD1_DAT1, SD1_DAT2, SD1_DAT3, SD_PWR, SDA0, SDA3

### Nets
3V3: C25.1 C29.2 J5.9(DET+) J6.14 J6.15 J10.14(LEDG+) J10.15(LEDY+) R16.2 U5.3(VDD) U6.5(IN)
5V: C30.2 J8.2 U8.1(IN)
DGND: C24.2 C25.2 C27.1 C28.1 C29.1 C30.1 C31.1 C32.1 C33.2 C34.2 C43.2 FL14.1 J5.6(VSS) J5.P1(SHIELD) J5.P2(SHIELD) J5.P3(SHIELD) J5.P4(SHIELD) J6.1 J6.4 J6.7 J6.10 J6.13 J7.2(D2S) J7.5(D1S) J7.8(D0S) J7.11(CKS) J7.17(GND) J7.20(SHIELD1) J7.21(SHIELD2) J7.22(SHIELD3) J7.23(SHIELD4) J8.1 J10.17(SHIELD1) J10.18(SHIELD2) R17.1 U5.4(GND) U8.3(GND) U9.3(GND) U9.8(GND) U10.3(GND) U10.8(GND) U11.5(GND) U11.10(GND)
DSI1_C_N: J6.5 ; port DSI1_C_N
DSI1_C_P: J6.6 ; port DSI1_C_P
DSI1_D0_N: J6.8 ; port DSI1_D0_N
DSI1_D0_P: J6.9 ; port DSI1_D0_P
DSI1_D1_N: J6.2 ; port DSI1_D1_N
DSI1_D1_P: J6.3 ; port DSI1_D1_P
Ethernet_nLED2: R22.2 ; port Ethernet_nLED2
Ethernet_nLED3: R21.2 ; port Ethernet_nLED3
Ethernet_Pair0_N: J10.10(TRD0-) ; port Ethernet_Pair0_N
Ethernet_Pair0_P: J10.11(TRD0+) ; port Ethernet_Pair0_P
Ethernet_Pair1_N: J10.5(TRD1-) ; port Ethernet_Pair1_N
Ethernet_Pair1_P: J10.4(TRD1+) ; port Ethernet_Pair1_P
Ethernet_Pair2_N: J10.2(TRD2-) ; port Ethernet_Pair2_N
Ethernet_Pair2_P: J10.3(TRD2+) ; port Ethernet_Pair2_P
Ethernet_Pair3_N: J10.9(TRD3-) ; port Ethernet_Pair3_N
Ethernet_Pair3_P: J10.8(TRD3+) ; port Ethernet_Pair3_P
HDMI0_CEC: U11.9(D3+) ; port HDMI0_CEC
HDMI0_CLK1_N: J7.12(CK-) U10.1(IO1_C)
HDMI0_CLK1_P: J7.10(CK+) U10.2(IC2_C)
HDMI0_CLK_N: U10.10(IO1_S) ; port HDMI0_CLK_N
HDMI0_CLK_P: U10.9(IC2_S) ; port HDMI0_CLK_P
HDMI0_HOTPLUG: U11.14(D1+) ; port HDMI0_HOTPLUG
HDMI0_SCL: U11.11(D2-) ; port HDMI0_SCL
HDMI0_SDA: U11.12(D2+) ; port HDMI0_SDA
HDMI0_TX0_N: U10.7(IO3_S) ; port HDMI0_TX0_N
HDMI0_TX0_P: U10.6(IO4_S) ; port HDMI0_TX0_P
HDMI0_TX1_N: U9.10(IO1_S) ; port HDMI0_TX1_N
HDMI0_TX01_N: J7.9(D0-) U10.4(IO3_C)
HDMI0_TX1_P: U9.9(IC2_S) ; port HDMI0_TX1_P
HDMI0_TX01_P: J7.7(D0+) U10.5(IO4_C)
HDMI0_TX2_N: U9.7(IO3_S) ; port HDMI0_TX2_N
HDMI0_TX2_P: U9.6(IO4_S) ; port HDMI0_TX2_P
HDMI0_TX11_N: J7.6(D1-) U9.1(IO1_C)
HDMI0_TX11_P: J7.4(D1+) U9.2(IC2_C)
HDMI0_TX21_N: J7.3(D2-) U9.4(IO3_C)
HDMI0_TX21_P: J7.1(D2+) U9.5(IO4_C)
HDMI_5V: C31.2 C32.2 C33.1 L12.2 U11.13(D1-) ; port HDMI_5V
SCL0: J6.11 ; port SCL0
SCL3: U5.2(SMCLK) ; port SCL3
SD1_CLK: J5.5(CLK) ; port SD1_CLK
SD1_CMD: J5.3(CMD) ; port SD1_CMD
SD1_DAT0: J5.7(DAT0) ; port SD1_DAT0
SD1_DAT1: J5.8(DAT1) ; port SD1_DAT1
SD1_DAT2: J5.1(DAT2) ; port SD1_DAT2
SD1_DAT3: J5.2(DAT3) ; port SD1_DAT3
SD_PWR: C24.1 C27.2 C28.2 FL14.4 J5.4(VDD) ; port SD_PWR
SDA0: J6.12 ; port SDA0
SDA3: U5.1(SMDATA) ; port SDA3
NetC34_1: C34.1 J7.18(+5V) U11.2(NC)
NetC43_1: C43.1 J10.1(CT1) J10.6(CT1) J10.7(CT3) J10.12(CT0)
NetFL14_2: FL14.2 U6.2(GND)
NetFL14_3: FL14.3 U6.1(OUT)
NetJ5_10: J5.10(DET-) R17.2 U6.4(EN)
NetJ7_13: J7.13(CEC) U11.6(NC)
NetJ7_15: J7.15(SCL) U11.4(NC)
NetJ7_16: J7.16(SDA) U11.3(NC)
NetJ7_19: J7.19(HPD/HEAC-) U11.1(NC)
NetJ8_3: J8.3 R16.1 U5.6(TACH)
NetJ8_4: J8.4 U5.5(PWM)
NetJ10_13: J10.13(LEDG-) R21.1
NetJ10_16: J10.16(LEDY-) R22.1
NetL12_1: L12.1 U8.2(OUT)

Not connected (* = marked no-connect by the designer): J6 16* 17* 18* 19* 20* 21* 22* 23* 24* 25* 26* 27* 28* 29* 30*; J7 14(UTILITY/HEAC+)*; U5 7(CLK)* 8(nALERT)*; U6 3(nFLG)*; U11 7(NC)* 8(D3-)*

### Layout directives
differential pair: DSI1_C_N, DSI1_C_P, DSI1_D0_N, DSI1_D0_P, DSI1_D1_N, DSI1_D1_P, Ethernet_Pair0_N, Ethernet_Pair0_P, Ethernet_Pair1_N, Ethernet_Pair1_P, Ethernet_Pair2_N, Ethernet_Pair2_P, Ethernet_Pair3_N, Ethernet_Pair3_P, HDMI0_CLK1_N, HDMI0_CLK1_P, HDMI0_CLK_N, HDMI0_CLK_P, HDMI0_TX0_N, HDMI0_TX0_P, HDMI0_TX01_N, HDMI0_TX1_N, HDMI0_TX01_P, HDMI0_TX1_P, HDMI0_TX2_N, HDMI0_TX2_P, HDMI0_TX11_N, HDMI0_TX11_P, HDMI0_TX21_N, HDMI0_TX21_P

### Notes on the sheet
- Display MIPI DSI
- MICRO SD CARD
- Fan Controller
- HDMI Current Limiting
- Display HDMI
- Ethernet

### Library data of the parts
C24 C25 C33 C34 C43 = C [1608]: MLCC - SMD/SMT 50V X5R +/-10% 1608(mm)
C27 C28 C31 C32 = C [3216]: MLCC - SMD/SMT 50V X5R +/-10% 3216(mm)
C29 C30 = C [2012]: MLCC - SMD/SMT 50V X5R +/-10% 2012(mm)
FL14 = SRF3225TP-501Y: as FL1 on sheet 3_Power_Boot
J5 = 503398-1892: Memory Card Connectors MICRO SD PUSH/PUSH NORMAL 1.28MM 8C; Maker: Molex
J6 = 4728: Raspberry Pi Accessories Replacement CSI/DSI Connector for Raspberry Pi - Repair Part; Maker: Adafruit
J7 = 2086581051: HDMI 2.1 Receptacle Connector 19 Position Surface Mount, Right Angle; Through Hole; Maker: Molex
J8 = 47053-1000: KK 254 Vertical Header, with Friction Lock, 4 Circuits, PC Tail Length 3.50mm, Bag; Maker: Molex; Plating: 151ConductorMaterial; Number of Contacts: 4; Gender: Male; Current Rating: 4A; Voltage Rating: 250V; Pitch: 2.54mm; Glow Wire Compliant: Non-compliant
J10 = 85793-1003: Gigabit Ethernet Connectors 8/8 RA Magnetic Jack Grn/Orange/Grn LED; Maker: Molex
L12 = BLM21PG121SN1D: as L1 on sheet 3_Power_Boot
R16 R17 = R [1005]_F: SMD  Chip Resistor +/-1% 1005(mm)
R21 R22 = R [1608]_J: SMD  Chip Resistor +/-5% 1608(mm)
U5 = EMC2301-1-ACZL-TR: Board Mount Temperature Sensors Single RPB-Based PWM Fan Speed CNTRL; Maker: Microchip
U6 = RT9742GGJ5: Power Switch ICs - Power Distribution 70mohm, 1A High-Side Power Switches with flag; Maker: Richtek
U8 = RT9742SNGV: Power Switch ICs - Power Distribution 70mohm, 0.5A High-Side Power Switches, Current Limiter; Maker: Richtek
U9 U10 = ESD224: ESD Suppressors / TVS Diodes Quad 0.5-pF, 3.6-V, 12-kV ESD protection diode for USB &amp; HDMI 10-USON -40 to 125; Maker: TI
U11 = TPD6E05U06: ESD Suppressors / TVS Diodes 6-CH lo cap IEC ESD protect diodes; Maker: TI

## Sheet 6_USB2.0.SchDoc
size A3; Organization: Altium Limited; Address1: L3, 12a Rodborough Rd; Address2: Frenchs Forest; Address3: NSW; Address4: Australia 2086
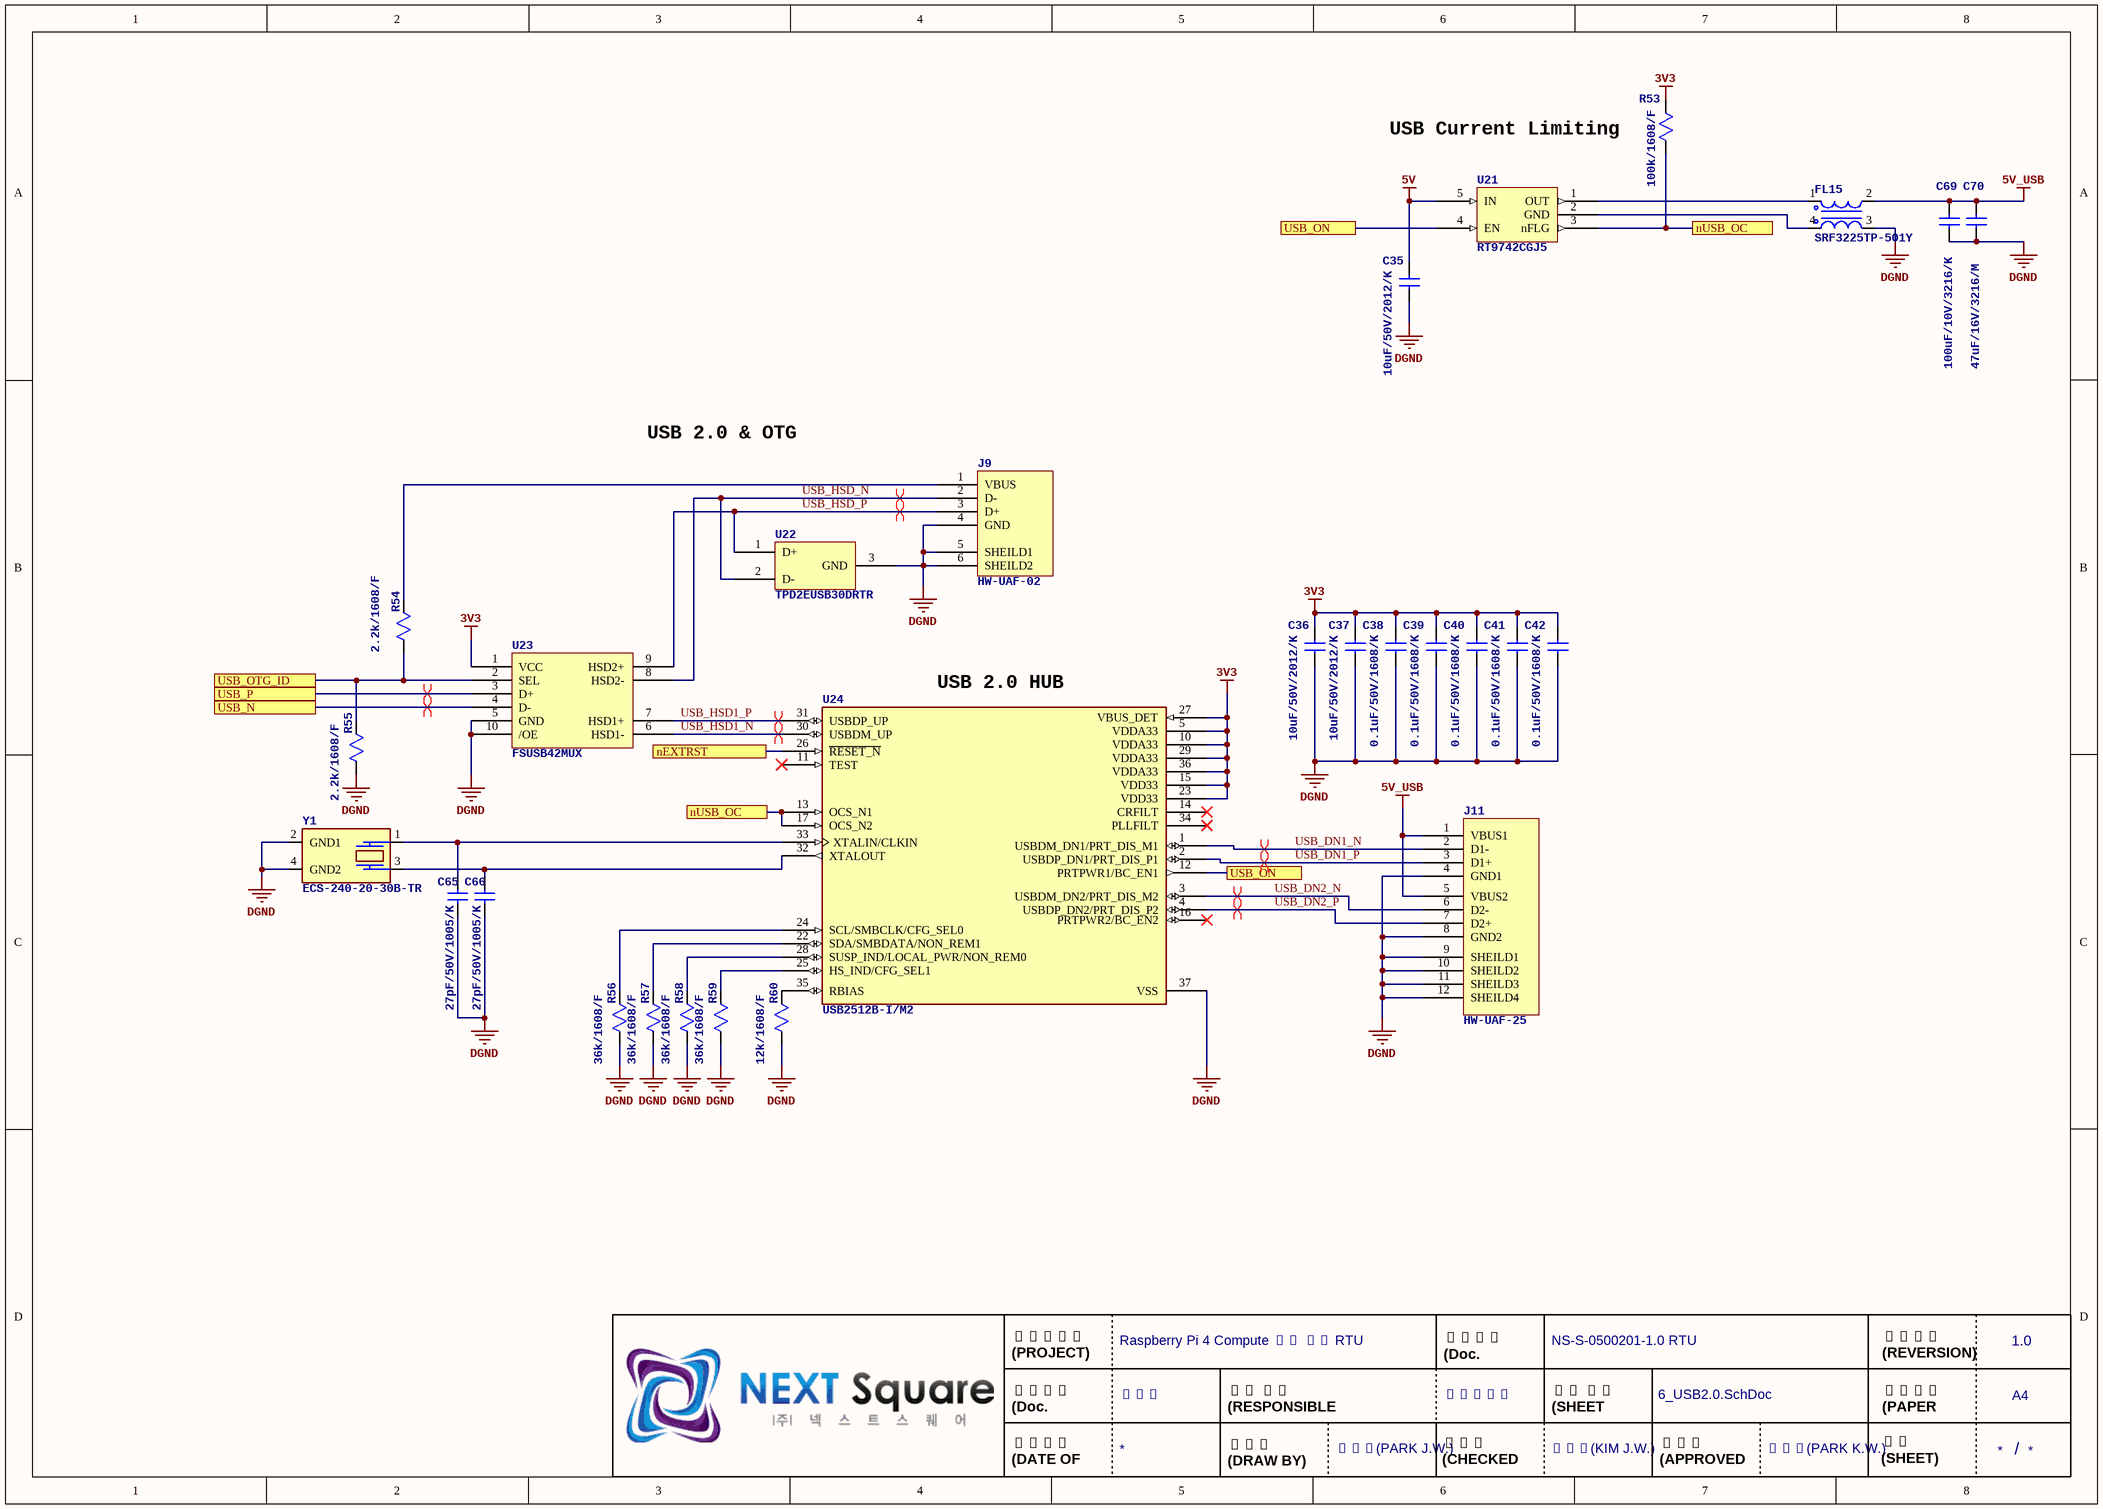
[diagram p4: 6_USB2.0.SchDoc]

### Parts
C35  value 10uF/50V/2012/K  [C2012]  (hidden comment: C [2012])
C36  value 10uF/50V/2012/K  [C2012]  (hidden comment: C [2012])
C37  value 10uF/50V/2012/K  [C2012]  (hidden comment: C [2012])
C38  value 0.1uF/50V/1608/K  [C1608]  (hidden comment: C [1608])
C39  value 0.1uF/50V/1608/K  [C1608]  (hidden comment: C [1608])
C40  value 0.1uF/50V/1608/K  [C1608]  (hidden comment: C [1608])
C41  value 0.1uF/50V/1608/K  [C1608]  (hidden comment: C [1608])
C42  value 0.1uF/50V/1608/K  [C1608]  (hidden comment: C [1608])
C65  value 27pF/50V/1005/K  [C1005]  (hidden comment: C [1005])  (no BOM)
C66  value 27pF/50V/1005/K  [C1005]  (hidden comment: C [1005])  (no BOM)
C69  value 100uF/10V/3216/K  [C3216]  (hidden comment: C [3216])
C70  value 47uF/16V/3216/M  [C3216]  (hidden comment: C [3216])
FL15  SRF3225TP-501Y  [SRF3225TP-501Y]
J9  HW-UAF-02  [HW-UAF-02]
J11  HW-UAF-25  [HW-UAF-25]
R53  value 100k/1608/F  [R1608]  (hidden comment: R [1608]_J)
R54  value 2.2k/1608/F  [R1608]  (hidden comment: R [1608]_J)
R55  value 2.2k/1608/F  [R1608]  (hidden comment: R [1608]_J)
R56  value 36k/1608/F  [R1608]  (hidden comment: R [1608]_J)
R57  value 36k/1608/F  [R1608]  (hidden comment: R [1608]_J)
R58  value 36k/1608/F  [R1608]  (hidden comment: R [1608]_J)
R59  value 36k/1608/F  [R1608]  (hidden comment: R [1608]_J)
R60  value 12k/1608/F  [R1608]  (hidden comment: R [1608]_J)
U21  RT9742CGJ5  [SOT23_5]
U22  TPD2EUSB30DRTR  [SOT23L]
U23  FSUSB42MUX  [MSOP10_0.5_5.0]
U24  USB2512B-I/M2  [QFN36_0.5_6X6_EP]
Y1  ECS-240-20-30B-TR  [ECS-240-20-30B-TR]

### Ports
nEXTRST, nUSB_OC, USB_N, USB_ON, USB_OTG_ID, USB_P

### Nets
3V3: C36.2 C37.2 C38.1 C39.1 C40.1 C41.1 C42.1 R53.1 U23.1(VCC) U24.5(VDDA33) U24.10(VDDA33) U24.15(VDD33) U24.23(VDD33) U24.27(VBUS_DET) U24.29(VDDA33) U24.36(VDDA33)
5V: C35.2 U21.5(IN)
5V_USB: C69.2 C70.2 FL15.2 J11.1(VBUS1) J11.5(VBUS2)
DGND: C35.1 C36.1 C37.1 C38.2 C39.2 C40.2 C41.2 C42.2 C65.2 C66.2 C69.1 C70.1 FL15.3 J9.4(GND) J9.5(SHEILD1) J9.6(SHEILD2) J11.4(GND1) J11.8(GND2) J11.9(SHEILD1) J11.10(SHEILD2) J11.11(SHEILD3) J11.12(SHEILD4) R55.1 R56.1 R57.1 R58.1 R59.1 R60.1 U22.3(GND) U23.5(GND) U23.10(/OE) U24.37(VSS) Y1.2(GND1) Y1.4(GND2)
nEXTRST: U24.26(~{RESET_N}) ; port nEXTRST
nUSB_OC: R53.2 U21.3(nFLG) U24.13(OCS_N1) U24.17(OCS_N2) ; port nUSB_OC
USB_DN1_N: J11.2(D1-) U24.1(USBDM_DN1/PRT_DIS_M1)
USB_DN1_P: J11.3(D1+) U24.2(USBDP_DN1/PRT_DIS_P1)
USB_DN2_N: J11.6(D2-) U24.3(USBDM_DN2/PRT_DIS_M2)
USB_DN2_P: J11.7(D2+) U24.4(USBDP_DN2/PRT_DIS_P2)
USB_HSD1_N: U23.6(HSD1-) U24.30(USBDM_UP)
USB_HSD1_P: U23.7(HSD1+) U24.31(USBDP_UP)
USB_HSD_N: J9.2(D-) U22.2(D-) U23.8(HSD2-)
USB_HSD_P: J9.3(D+) U22.1(D+) U23.9(HSD2+)
USB_N: U23.4(D-) ; port USB_N
USB_ON: U21.4(EN) U24.12(PRTPWR1/BC_EN1) ; port USB_ON
USB_OTG_ID: R54.1 R55.2 U23.2(SEL) ; port USB_OTG_ID
USB_P: U23.3(D+) ; port USB_P
NetC65_1: C65.1 U24.33(XTALIN/CLKIN) Y1.1(IN/OUT)
NetC66_1: C66.1 U24.32(XTALOUT) Y1.3(OUT/IN)
NetFL15_1: FL15.1 U21.1(OUT)
NetFL15_4: FL15.4 U21.2(GND)
NetJ9_1: J9.1(VBUS) R54.2
NetR56_2: R56.2 U24.24(SCL/SMBCLK/CFG_SEL0)
NetR57_2: R57.2 U24.22(SDA/SMBDATA/NON_REM1)
NetR58_2: R58.2 U24.28(SUSP_IND/LOCAL_PWR/NON_REM0)
NetR59_2: R59.2 U24.25(HS_IND/CFG_SEL1)
NetR60_2: R60.2 U24.35(RBIAS)

Not connected (* = marked no-connect by the designer): U24 11(TEST)* 14(CRFILT)* 16(PRTPWR2/BC_EN2)* 34(PLLFILT)*

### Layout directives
differential pair: USB_DN1_N, USB_DN1_P, USB_DN2_N, USB_DN2_P, USB_HSD1_N, USB_HSD1_P, USB_HSD_N, USB_HSD_P, USB_N, USB_P

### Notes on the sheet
- USB Current Limiting
- USB 2.0 & OTG
- (near U24) USB 2.0 HUB

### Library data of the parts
C35-C37 = C [2012]: MLCC - SMD/SMT 50V X5R +/-10% 2012(mm)
C38-C42 = C [1608]: MLCC - SMD/SMT 50V X5R +/-10% 1608(mm)
C65 C66 = C [1005]: MLCC - SMD/SMT 50V X5R +/-10% 1005(mm)
C69 C70 = C [3216]: MLCC - SMD/SMT 50V X5R +/-10% 3216(mm)
FL15 = SRF3225TP-501Y: as FL1 on sheet 3_Power_Boot
J9 = HW-UAF-02: USB 2.0 A/F Connector, Right angle
J11 = HW-UAF-25: USB 2.0 A/F 2 stack Connector, Right angle
R53-R60 = R [1608]_J: SMD  Chip Resistor +/-5% 1608(mm)
U21 = RT9742CGJ5: Power Switch ICs - Power Distribution 70mohm, 2A High-Side Power Switches with flag; Maker: Richtek
U22 = TPD2EUSB30DRTR: ESD Suppressors / TVS Diodes 2Ch ESD Solution; PartNo.: Package; Maker: TI
U23 = FSUSB42MUX: USB Switch ICs Low Power, Two-Port USB 2.0 (480Mbps); Maker: ONSEMI
U24 = USB2512B-I/M2: USB Interface IC 2-Port USB 2.0 Hi-Speed Hub Cont; Maker: Microchip
Y1 = ECS-240-20-30B-TR: Crystal 24MHz ±30ppm (Tol) ±50ppm (Stability) 20pF FUND 80Ohm 4-Pin Mini-SMD T/R; Maker: ECS

## Sheet 7_USB3.0.SchDoc
size A3; SheetNumber: 6; SheetTotal: 9; Organization: Altium Limited; Address1: L3, 12a Rodborough Rd; Address2: Frenchs Forest; Address3: NSW; Address4: Australia 2086
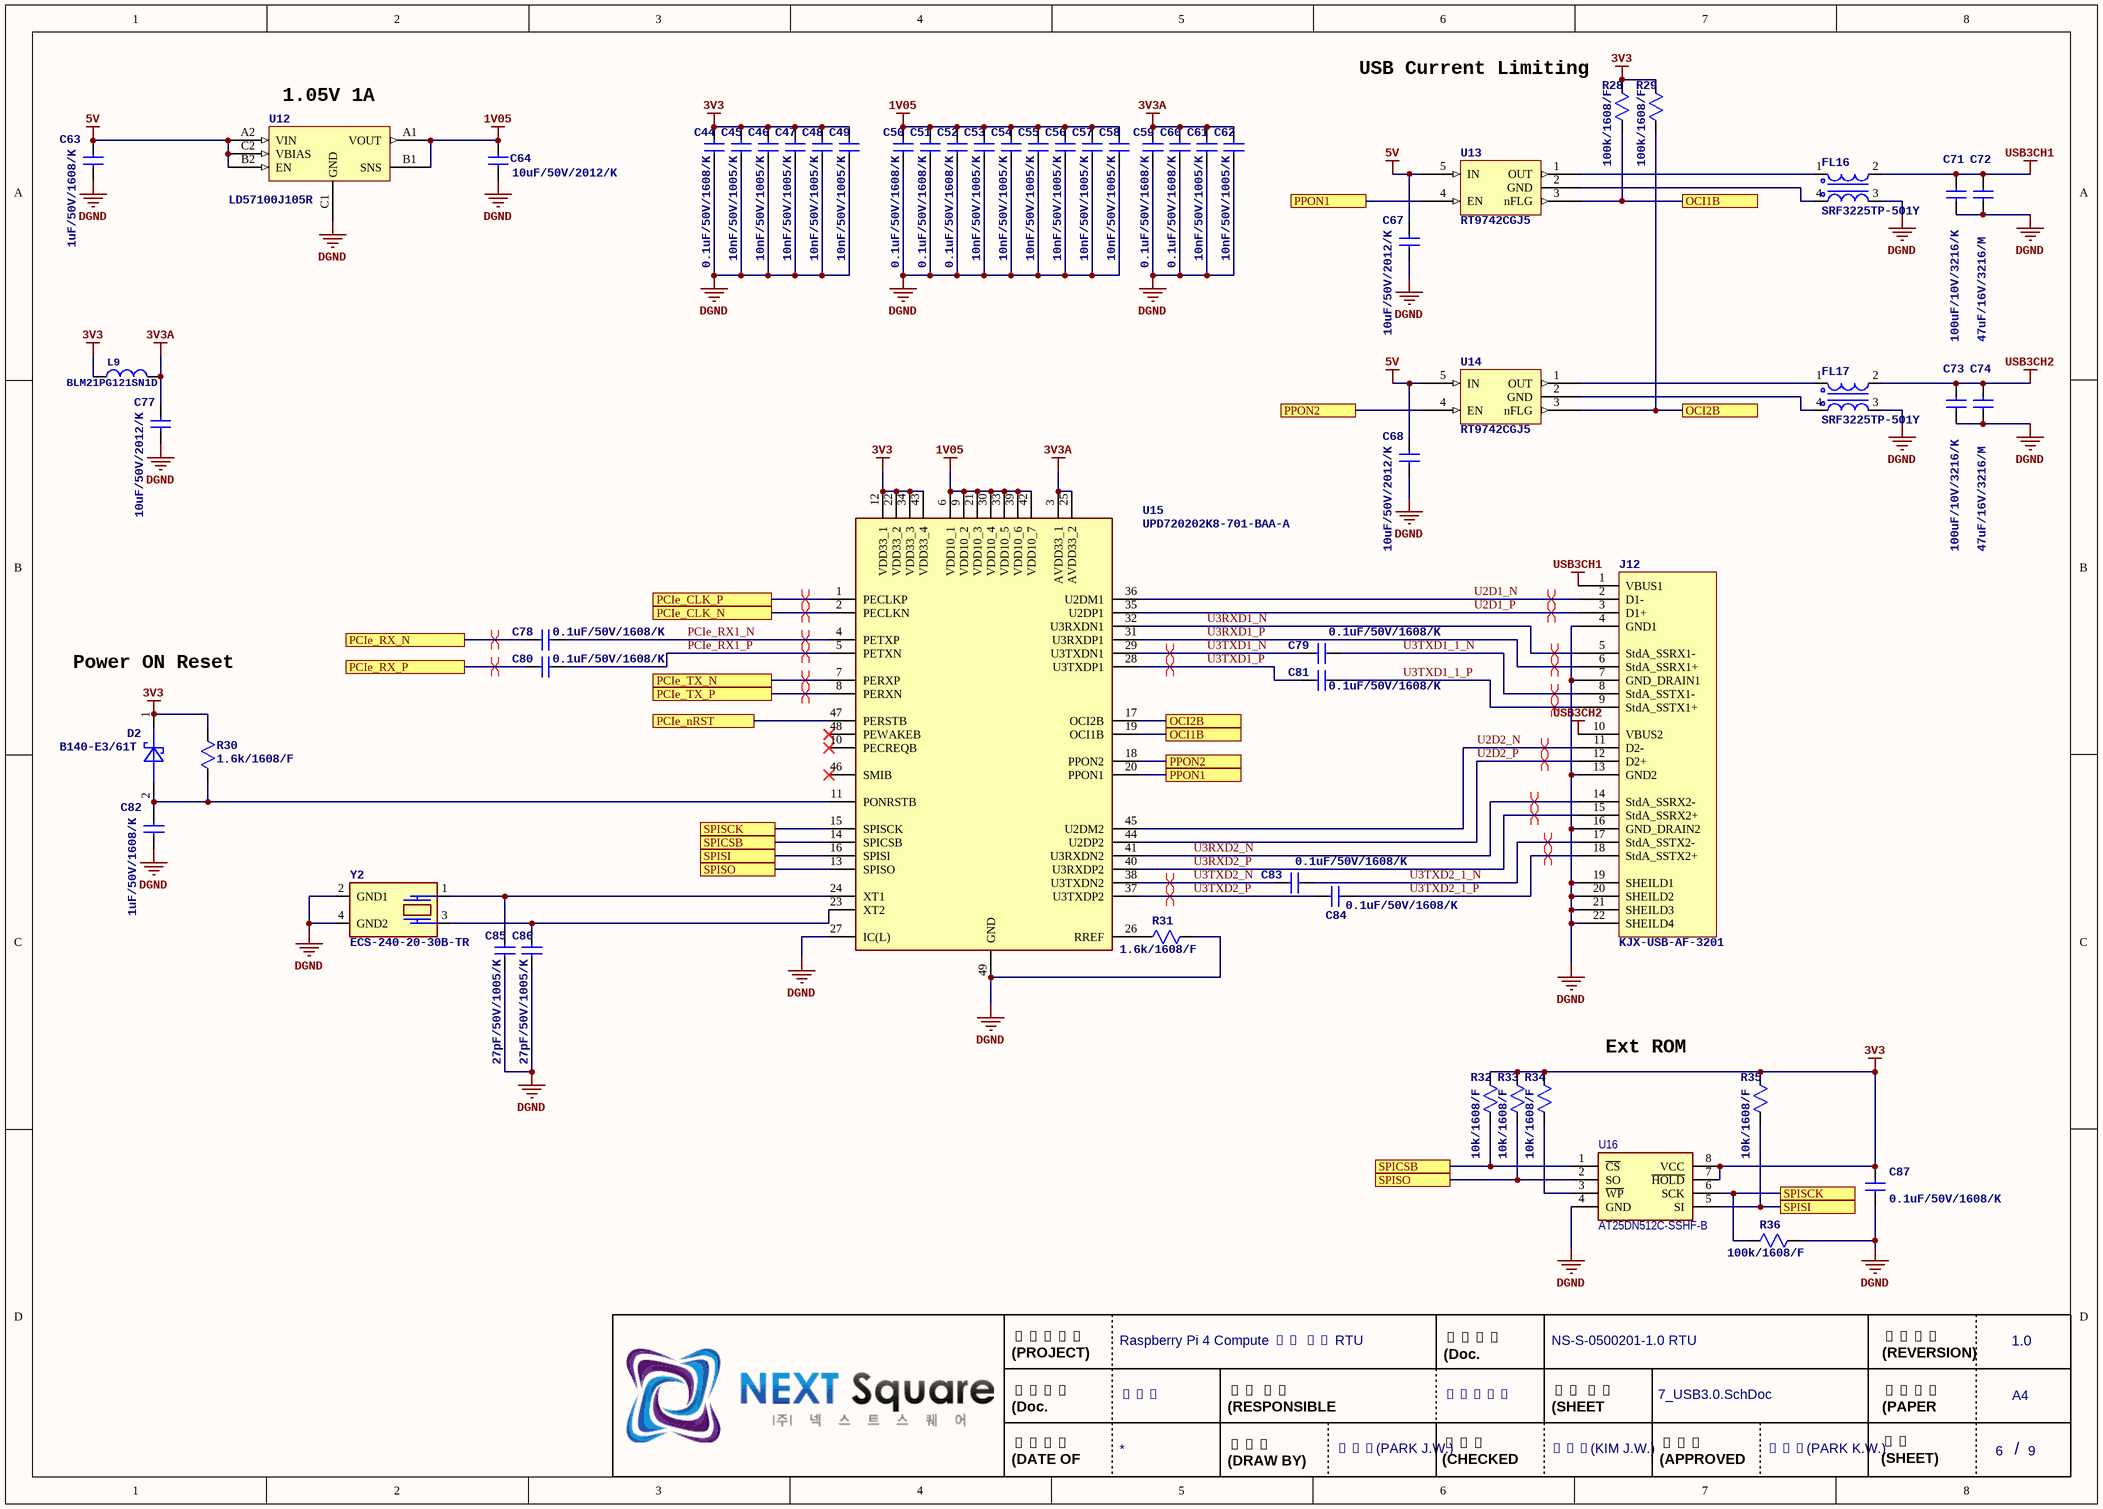
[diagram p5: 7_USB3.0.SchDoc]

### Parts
C44  value 0.1uF/50V/1608/K  [C1608]  (hidden comment: C [1608])
C45  value 10nF/50V/1005/K  [C1005]  (hidden comment: C [1005])  (no BOM)
C46  value 10nF/50V/1005/K  [C1005]  (hidden comment: C [1005])  (no BOM)
C47  value 10nF/50V/1005/K  [C1005]  (hidden comment: C [1005])  (no BOM)
C48  value 10nF/50V/1005/K  [C1005]  (hidden comment: C [1005])  (no BOM)
C49  value 10nF/50V/1005/K  [C1005]  (hidden comment: C [1005])  (no BOM)
C50  value 0.1uF/50V/1608/K  [C1608]  (hidden comment: C [1608])
C51  value 0.1uF/50V/1608/K  [C1608]  (hidden comment: C [1608])
C52  value 0.1uF/50V/1608/K  [C1608]  (hidden comment: C [1608])
C53  value 10nF/50V/1005/K  [C1005]  (hidden comment: C [1005])  (no BOM)
C54  value 10nF/50V/1005/K  [C1005]  (hidden comment: C [1005])  (no BOM)
C55  value 10nF/50V/1005/K  [C1005]  (hidden comment: C [1005])  (no BOM)
C56  value 10nF/50V/1005/K  [C1005]  (hidden comment: C [1005])  (no BOM)
C57  value 10nF/50V/1005/K  [C1005]  (hidden comment: C [1005])  (no BOM)
C58  value 10nF/50V/1005/K  [C1005]  (hidden comment: C [1005])  (no BOM)
C59  value 0.1uF/50V/1608/K  [C1608]  (hidden comment: C [1608])
C60  value 0.1uF/50V/1608/K  [C1608]  (hidden comment: C [1608])
C61  value 10nF/50V/1005/K  [C1005]  (hidden comment: C [1005])  (no BOM)
C62  value 10nF/50V/1005/K  [C1005]  (hidden comment: C [1005])  (no BOM)
C63  value 1uF/50V/1608/K  [C1608]  (hidden comment: C [1608])
C64  value 10uF/50V/2012/K  [C2012]  (hidden comment: C [2012])
C67  value 10uF/50V/2012/K  [C2012]  (hidden comment: C [2012])
C68  value 10uF/50V/2012/K  [C2012]  (hidden comment: C [2012])
C71  value 100uF/10V/3216/K  [C3216]  (hidden comment: C [3216])
C72  value 47uF/16V/3216/M  [C3216]  (hidden comment: C [3216])
C73  value 100uF/10V/3216/K  [C3216]  (hidden comment: C [3216])
C74  value 47uF/16V/3216/M  [C3216]  (hidden comment: C [3216])
C77  value 10uF/50V/2012/K  [C2012]  (hidden comment: C [2012])
C78  value 0.1uF/50V/1608/K  [C1608]  (hidden comment: C [1608])
C79  value 0.1uF/50V/1608/K  [C1608]  (hidden comment: C [1608])
C80  value 0.1uF/50V/1608/K  [C1608]  (hidden comment: C [1608])
C81  value 0.1uF/50V/1608/K  [C1608]  (hidden comment: C [1608])
C82  value 1uF/50V/1608/K  [C1608]  (hidden comment: C [1608])
C83  value 0.1uF/50V/1608/K  [C1608]  (hidden comment: C [1608])
C84  value 0.1uF/50V/1608/K  [C1608]  (hidden comment: C [1608])
C85  value 27pF/50V/1005/K  [C1005]  (hidden comment: C [1005])  (no BOM)
C86  value 27pF/50V/1005/K  [C1005]  (hidden comment: C [1005])  (no BOM)
C87  value 0.1uF/50V/1608/K  [C1608]  (hidden comment: C [1608])
D2  B140-E3/61T  [DO-214AC(SMA)_21]
FL16  SRF3225TP-501Y  [SRF3225TP-501Y]
FL17  SRF3225TP-501Y  [SRF3225TP-501Y]
J12  KJX-USB-AF-3201  [KJX-USB-AF-3201]
L9  BLM21PG121SN1D  [L2012]
R28  value 100k/1608/F  [R1608]  (hidden comment: R [1608]_J)
R29  value 100k/1608/F  [R1608]  (hidden comment: R [1608]_J)
R30  value 1.6k/1608/F  [R1608]  (hidden comment: R [1608]_J)
R31  value 1.6k/1608/F  [R1608]  (hidden comment: R [1608]_J)
R32  value 10k/1608/F  [R1608]  (hidden comment: R [1608]_J)
R33  value 10k/1608/F  [R1608]  (hidden comment: R [1608]_J)
R34  value 10k/1608/F  [R1608]  (hidden comment: R [1608]_J)
R35  value 10k/1608/F  [R1608]  (hidden comment: R [1608]_J)
R36  value 100k/1608/F  [R1608]  (hidden comment: R [1608]_J)
U12  LD57100J105R  [WLCSP6_0.4P]
U13  RT9742CGJ5  [SOT23_5]
U14  RT9742CGJ5  [SOT23_5]
U15  UPD720202K8-701-BAA-A  [QFN48_0.5_7X7_EP]
U16  AT25DN512C-SSHF-B  [SOIC8_1.27_6.0]
Y2  ECS-240-20-30B-TR  [ECS-240-20-30B-TR]

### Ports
OCI1B, OCI2B, PCIe_CLK_N, PCIe_CLK_P, PCIe_nRST, PCIe_RX_N, PCIe_RX_P, PCIe_TX_N, PCIe_TX_P, PPON1, PPON2, SPICSB, SPISCK, SPISI, SPISO

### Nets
1V05: C50.1 C51.1 C52.1 C53.1 C54.1 C55.1 C56.1 C57.1 C58.1 C64.1 U12.A1(VOUT) U12.B1(SNS) U15.6(VDD10_1) U15.9(VDD10_2) U15.21(VDD10_3) U15.30(VDD10_4) U15.33(VDD10_5) U15.39(VDD10_6) U15.42(VDD10_7)
3V3: C44.1 C45.1 C46.1 C47.1 C48.1 C49.1 C87.1 D2.1(Cathode) L9.1 R28.1 R29.1 R30.1 R32.1 R33.1 R34.1 R35.1 U15.12(VDD33_1) U15.22(VDD33_2) U15.34(VDD33_3) U15.43(VDD33_4) U16.7(~{HOLD}) U16.8(VCC)
3V3A: C59.1 C60.1 C61.1 C62.1 C77.2 L9.2 U15.3(AVDD33_1) U15.25(AVDD33_2)
5V: C63.1 C67.2 C68.2 U12.A2(VIN) U12.B2(EN) U12.C2(VBIAS) U13.5(IN) U14.5(IN)
DGND: C44.2 C45.2 C46.2 C47.2 C48.2 C49.2 C50.2 C51.2 C52.2 C53.2 C54.2 C55.2 C56.2 C57.2 C58.2 C59.2 C60.2 C61.2 C62.2 C63.2 C64.2 C67.1 C68.1 C71.1 C72.1 C73.1 C74.1 C77.1 C82.2 C85.2 C86.2 C87.2 FL16.3 FL17.3 J12.4(GND1) J12.7(GND_DRAIN1) J12.13(GND2) J12.16(GND_DRAIN2) J12.19(SHEILD1) J12.20(SHEILD2) J12.21(SHEILD3) J12.22(SHEILD4) R31.1 R36.1 U12.C1(GND) U15.27(IC(L)) U15.49(GND) U16.4(GND) Y2.2(GND1) Y2.4(GND2)
USB3CH1: C71.2 C72.2 FL16.2 J12.1(VBUS1)
USB3CH2: C73.2 C74.2 FL17.2 J12.10(VBUS2)
OCI1B: R28.2 U13.3(nFLG) U15.19(OCI1B) ; port OCI1B
OCI2B: R29.2 U14.3(nFLG) U15.17(OCI2B) ; port OCI2B
PCIe_CLK_N: U15.2(PECLKN) ; port PCIe_CLK_N
PCIe_CLK_P: U15.1(PECLKP) ; port PCIe_CLK_P
PCIe_nRST: U15.47(PERSTB) ; port PCIe_nRST
PCIe_RX1_N: C78.2 U15.4(PETXP)
PCIe_RX1_P: C80.2 U15.5(PETXN)
PCIe_RX_N: C78.1 ; port PCIe_RX_N
PCIe_RX_P: C80.1 ; port PCIe_RX_P
PCIe_TX_N: U15.7(PERXP) ; port PCIe_TX_N
PCIe_TX_P: U15.8(PERXN) ; port PCIe_TX_P
PPON1: U13.4(EN) U15.20(PPON1) ; port PPON1
PPON2: U14.4(EN) U15.18(PPON2) ; port PPON2
SPICSB: R32.2 U15.14(SPICSB) U16.1(~{CS}) ; port SPICSB
SPISCK: R36.2 U15.15(SPISCK) U16.6(SCK) ; port SPISCK
SPISI: R35.2 U15.16(SPISI) U16.5(SI) ; port SPISI
SPISO: R33.2 U15.13(SPISO) U16.2(SO) ; port SPISO
U2D1_N: J12.2(D1-) U15.36(U2DM1)
U2D1_P: J12.3(D1+) U15.35(U2DP1)
U2D2_N: J12.11(D2-) U15.45(U2DM2)
U2D2_P: J12.12(D2+) U15.44(U2DP2)
U3RXD1_N: J12.5(StdA_SSRX1-) U15.32(U3RXDN1)
U3RXD1_P: J12.6(StdA_SSRX1+) U15.31(U3RXDP1)
U3RXD2_N: J12.14(StdA_SSRX2-) U15.41(U3RXDN2)
U3RXD2_P: J12.15(StdA_SSRX2+) U15.40(U3RXDP2)
U3TXD1_1_N: C79.2 J12.8(StdA_SSTX1-)
U3TXD1_1_P: C81.2 J12.9(StdA_SSTX1+)
U3TXD1_N: C79.1 U15.29(U3TXDN1)
U3TXD1_P: C81.1 U15.28(U3TXDP1)
U3TXD2_1_N: C83.2 J12.17(StdA_SSTX2-)
U3TXD2_1_P: C84.2 J12.18(StdA_SSTX2+)
U3TXD2_N: C83.1 U15.38(U3TXDN2)
U3TXD2_P: C84.1 U15.37(U3TXDP2)
NetC82_1: C82.1 D2.2(Anode) R30.2 U15.11(PONRSTB)
NetC85_1: C85.1 U15.24(XT1) Y2.1(IN/OUT)
NetC86_1: C86.1 U15.23(XT2) Y2.3(OUT/IN)
NetFL16_1: FL16.1 U13.1(OUT)
NetFL16_4: FL16.4 U13.2(GND)
NetFL17_1: FL17.1 U14.1(OUT)
NetFL17_4: FL17.4 U14.2(GND)
NetR31_2: R31.2 U15.26(RREF)
NetR34_2: R34.2 U16.3(~{WP})

Not connected (* = marked no-connect by the designer): U15 10(PECREQB)* 46(SMIB)* 48(PEWAKEB)*

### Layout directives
differential pair: PCIe_CLK_N, PCIe_CLK_P, PCIe_RX1_N, PCIe_RX1_P, PCIe_RX_N, PCIe_RX_P, PCIe_TX_N, PCIe_TX_P, U2D1_N, U2D1_P, U2D2_N, U2D2_P, U3RXD1_N, U3RXD1_P, U3RXD2_N, U3RXD2_P, U3TXD1_1_N, U3TXD1_1_P, U3TXD1_N, U3TXD1_P, U3TXD2_1_N, U3TXD2_1_P, U3TXD2_N, U3TXD2_P

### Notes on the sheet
- (near U12) 1.05V 1A
- USB Current Limiting
- Power ON Reset
- Ext ROM

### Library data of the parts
C44 C50-C52 C59 C60 C63 C78-C84 C87 = C [1608]: MLCC - SMD/SMT 50V X5R +/-10% 1608(mm)
C45-C49 C53-C58 C61 C62 C85 C86 = C [1005]: MLCC - SMD/SMT 50V X5R +/-10% 1005(mm)
C64 C67 C68 C77 = C [2012]: MLCC - SMD/SMT 50V X5R +/-10% 2012(mm)
C71-C74 = C [3216]: MLCC - SMD/SMT 50V X5R +/-10% 3216(mm)
D2 = B140-E3/61T: Schottky Diodes & Rectifiers 1.0 Amp 40 Volt; Maker: Vishay
FL16 FL17 = SRF3225TP-501Y: as FL1 on sheet 3_Power_Boot
J12 = KJX-USB-AF-3201: USB 3.0 A/F 2 stack Connector, Right angle
L9 = BLM21PG121SN1D: as L1 on sheet 3_Power_Boot
R28-R36 = R [1608]_J: SMD  Chip Resistor +/-5% 1608(mm)
U12 = LD57100J105R: LDO Voltage Regulators 3V~5.5V to 1.05V 1A ultra low-dropout LDO bias; Maker: STMicroelectronics
U13 U14 = RT9742CGJ5: as U21 on sheet 6_USB2.0
U15 = UPD720202K8-701-BAA-A: PD720202 is a USB host controller LSI compatible with the USB 3.0 and xHCI (eXtensible Host Controller Interface) 1.0 specifications. The system bus is compatible with the PCIe Gen2 specification. The controller provides two USB ports with LS (Low-Speed) / FS (Full-Speed) / HS (High-Speed) / SS (SuperSpeed) support.PD720202 comes in a 48-pin QFN package and has the following improvements over previous products.	Reduced power consumption in low-power mode to 4.5mW, a reduction of 90% compared with Renesas; Manufacturer_Name: Renesas Electronics; Geometry.Height: 0.9mm
U16 = AT25DN512C-SSHF-B: NOR Flash 512 Kbit, 3.0V (2.3V to 3.6V), -40C to 85C, SOIC-N 150mil (Tube), Single, Dual SPI NOR flash; Maker: Renesas / Dialog
Y2 = ECS-240-20-30B-TR: as Y1 on sheet 6_USB2.0

## Sheet 8_CANFD.SchDoc
size A3; SheetNumber: 7; SheetTotal: 8; Organization: Altium Limited; Address1: L3, 12a Rodborough Rd; Address2: Frenchs Forest; Address3: NSW; Address4: Australia 2086
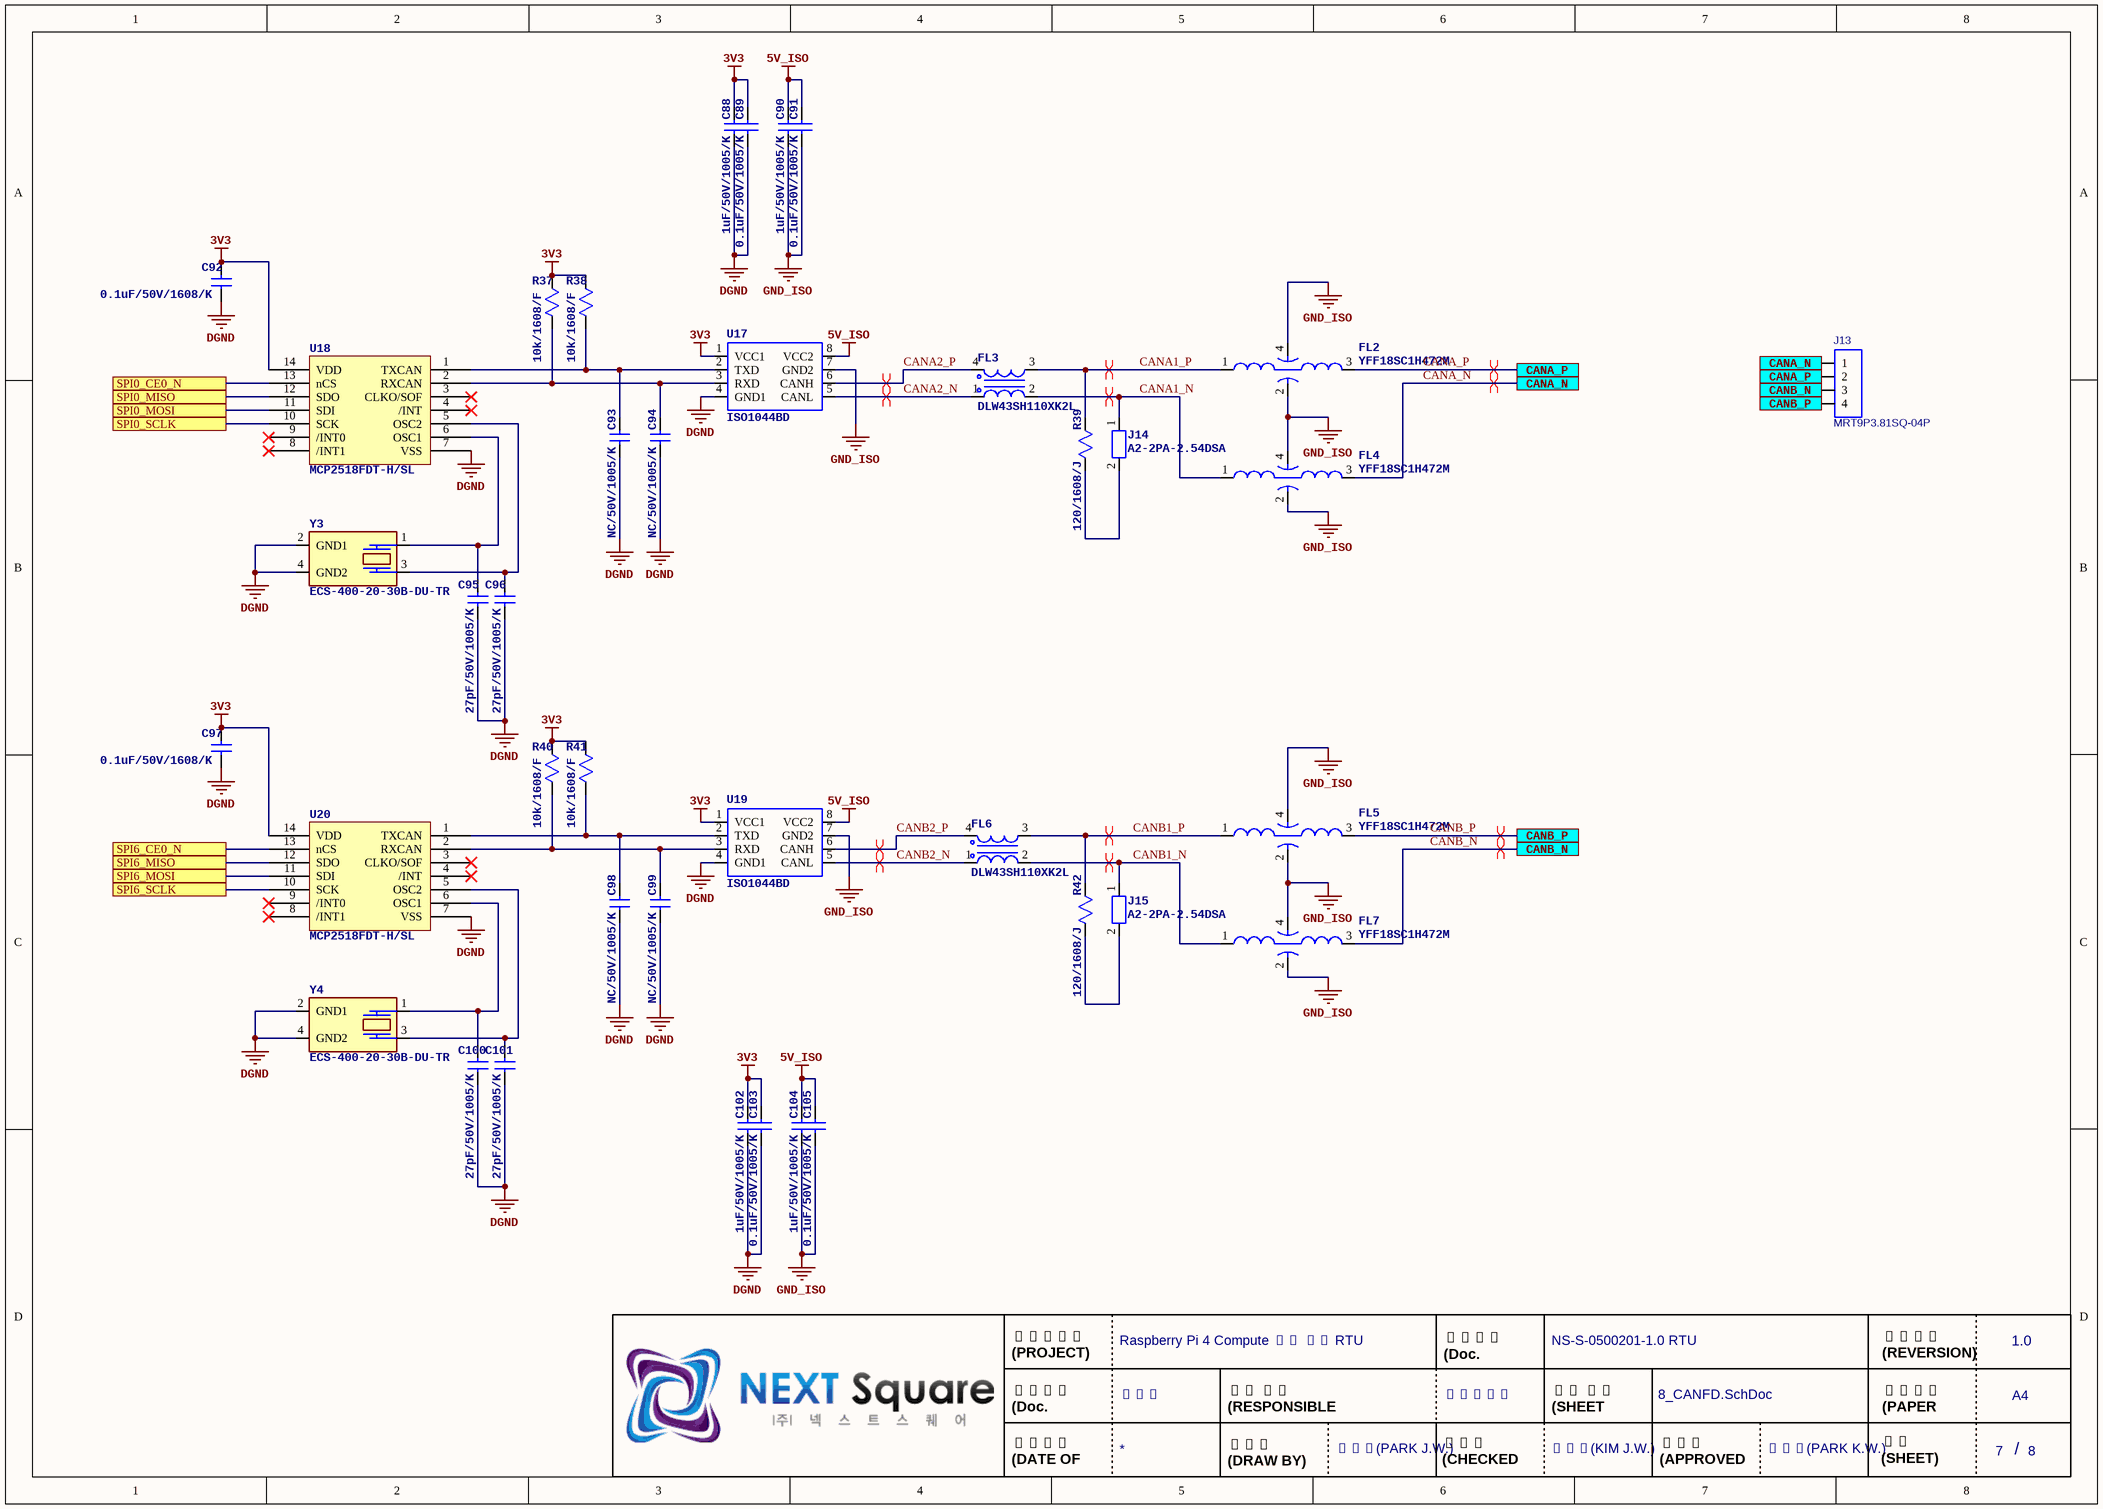
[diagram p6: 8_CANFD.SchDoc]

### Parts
C88  value 1uF/50V/1005/K  [C1005]  (hidden comment: C [1005])
C89  value 0.1uF/50V/1005/K  [C1005]  (hidden comment: C [1005])
C90  value 1uF/50V/1005/K  [C1005]  (hidden comment: C [1005])
C91  value 0.1uF/50V/1005/K  [C1005]  (hidden comment: C [1005])
C92  value 0.1uF/50V/1608/K  [C1608]  (hidden comment: C [1608])
C93  value NC/50V/1005/K  [C1005]  (hidden comment: C [1005])
C94  value NC/50V/1005/K  [C1005]  (hidden comment: C [1005])
C95  value 27pF/50V/1005/K  [C1005]  (hidden comment: C [1005])  (no BOM)
C96  value 27pF/50V/1005/K  [C1005]  (hidden comment: C [1005])  (no BOM)
C97  value 0.1uF/50V/1608/K  [C1608]  (hidden comment: C [1608])
C98  value NC/50V/1005/K  [C1005]  (hidden comment: C [1005])
C99  value NC/50V/1005/K  [C1005]  (hidden comment: C [1005])
C100  value 27pF/50V/1005/K  [C1005]  (hidden comment: C [1005])  (no BOM)
C101  value 27pF/50V/1005/K  [C1005]  (hidden comment: C [1005])  (no BOM)
C102  value 1uF/50V/1005/K  [C1005]  (hidden comment: C [1005])
C103  value 0.1uF/50V/1005/K  [C1005]  (hidden comment: C [1005])
C104  value 1uF/50V/1005/K  [C1005]  (hidden comment: C [1005])
C105  value 0.1uF/50V/1005/K  [C1005]  (hidden comment: C [1005])
FL2  YFF18SC1H472M  [YFF18SC1H472M]
FL3  DLW43SH110XK2L  [DLW43SH110XK2L]
FL4  YFF18SC1H472M  [YFF18SC1H472M]
FL5  YFF18SC1H472M  [YFF18SC1H472M]
FL6  DLW43SH110XK2L  [DLW43SH110XK2L]
FL7  YFF18SC1H472M  [YFF18SC1H472M]
J13  MRT9P3.81SQ-04P  [MRT9P3.81SQ-04P]
J14  A2-2PA-2.54DSA  [A2-2PA-2.54DSA]
J15  A2-2PA-2.54DSA  [A2-2PA-2.54DSA]
R37  value 10k/1608/F  [R1608]  (hidden comment: R [1608]_J)
R38  value 10k/1608/F  [R1608]  (hidden comment: R [1608]_J)
R39  value 120/1608/J  [R1608]  (hidden comment: R [1608]_J)
R40  value 10k/1608/F  [R1608]  (hidden comment: R [1608]_J)
R41  value 10k/1608/F  [R1608]  (hidden comment: R [1608]_J)
R42  value 120/1608/J  [R1608]  (hidden comment: R [1608]_J)
U17  ISO1044BD  [SOIC8_1.27_6.0]
U18  MCP2518FDT-H/SL  [SOIC14_1.27_6.0]
U19  ISO1044BD  [SOIC8_1.27_6.0]
U20  MCP2518FDT-H/SL  [SOIC14_1.27_6.0]
Y3  ECS-400-20-30B-DU-TR  [ECS-400-20-30B-DU-TR]
Y4  ECS-400-20-30B-DU-TR  [ECS-400-20-30B-DU-TR]

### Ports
CANA_N, CANA_P, CANB_N, CANB_P, SPI0_CE0_N, SPI0_MISO, SPI0_MOSI, SPI0_SCLK, SPI6_CE0_N, SPI6_MISO, SPI6_MOSI, SPI6_SCLK

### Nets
3V3: C88.1 C89.1 C92.1 C97.1 C102.1 C103.1 R37.1 R38.1 R40.1 R41.1 U17.1(VCC1) U18.14(VDD) U19.1(VCC1) U20.14(VDD)
5V_ISO: C90.1 C91.1 C104.1 C105.1 U17.8(VCC2) U19.8(VCC2)
DGND: C88.2 C89.2 C92.2 C93.2 C94.2 C95.2 C96.2 C97.2 C98.2 C99.2 C100.2 C101.2 C102.2 C103.2 U17.4(GND1) U18.7(VSS) U19.4(GND1) U20.7(VSS) Y3.2(GND1) Y3.4(GND2) Y4.2(GND1) Y4.4(GND2)
GND_ISO: C90.2 C91.2 C104.2 C105.2 FL2.2(GND_1) FL2.4(GND_2) FL4.2(GND_1) FL4.4(GND_2) FL5.2(GND_1) FL5.4(GND_2) FL7.2(GND_1) FL7.4(GND_2) U17.7(GND2) U19.7(GND2)
CANA1_N: FL3.2 FL4.1(IN/OUT) J14.1
CANA1_P: FL2.1(IN/OUT) FL3.3 R39.2
CANA2_N: FL3.1 U17.5(CANL)
CANA2_P: FL3.4 U17.6(CANH)
CANA_N: FL4.3(OUT/IN) J13.1 ; port CANA_N
CANA_P: FL2.3(OUT/IN) J13.2 ; port CANA_P
CANB1_N: FL6.2 FL7.1(IN/OUT) J15.1
CANB1_P: FL5.1(IN/OUT) FL6.3 R42.2
CANB2_N: FL6.1 U19.5(CANL)
CANB2_P: FL6.4 U19.6(CANH)
CANB_N: FL7.3(OUT/IN) J13.3 ; port CANB_N
CANB_P: FL5.3(OUT/IN) J13.4 ; port CANB_P
SPI0_CE0_N: U18.13(nCS) ; port SPI0_CE0_N
SPI0_MISO: U18.12(SDO) ; port SPI0_MISO
SPI0_MOSI: U18.11(SDI) ; port SPI0_MOSI
SPI0_SCLK: U18.10(SCK) ; port SPI0_SCLK
SPI6_CE0_N: U20.13(nCS) ; port SPI6_CE0_N
SPI6_MISO: U20.12(SDO) ; port SPI6_MISO
SPI6_MOSI: U20.11(SDI) ; port SPI6_MOSI
SPI6_SCLK: U20.10(SCK) ; port SPI6_SCLK
NetC93_1: C93.1 R38.2 U17.2(TXD) U18.1(TXCAN)
NetC94_1: C94.1 R37.2 U17.3(RXD) U18.2(RXCAN)
NetC95_1: C95.1 U18.6(OSC1) Y3.1(IN/OUT)
NetC96_1: C96.1 U18.5(OSC2) Y3.3(OUT/IN)
NetC98_1: C98.1 R41.2 U19.2(TXD) U20.1(TXCAN)
NetC99_1: C99.1 R40.2 U19.3(RXD) U20.2(RXCAN)
NetC100_1: C100.1 U20.6(OSC1) Y4.1(IN/OUT)
NetC101_1: C101.1 U20.5(OSC2) Y4.3(OUT/IN)
NetJ14_2: J14.2 R39.1
NetJ15_2: J15.2 R42.1

Not connected (* = marked no-connect by the designer): U18 3(CLKO/SOF)* 4(/INT)* 8(/INT1)* 9(/INT0)*; U20 3(CLKO/SOF)* 4(/INT)* 8(/INT1)* 9(/INT0)*

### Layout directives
differential pair: CANA1_N, CANA1_P, CANA2_N, CANA2_P, CANA_N, CANA_P, CANB1_N, CANB1_P, CANB2_N, CANB2_P, CANB_N, CANB_P

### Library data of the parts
C88-C91 C93-C96 C98-C105 = C [1005]: MLCC - SMD/SMT 50V X5R +/-10% 1005(mm)
C92 C97 = C [1608]: MLCC - SMD/SMT 50V X5R +/-10% 1608(mm)
FL2 FL4 FL5 FL7 = YFF18SC1H222M: Eia Case Size: 0603, Voltage: 50, Cap Value: 472, Tol: +/-20%, Thickness: 0.60 ± 0.10; Manufacturer_Name: TDK; Manufacturer_Part_Number: YFF18SC1H222MT0H0N; Capacitance: 4.7nF; Voltage Rating: 50V; Current: 1A; DC Resistance (DCR): 300mR; Insertion Loss: 30dB; Tolerance: 20%; Value: 4700pF
FL3 FL6 = DLW43SH110XK2L: CMC 11UH 360MA 2LN SMD AEC-Q200; Manufacturer_Name: Murata Electronics; Manufacturer: Murata; Number of Lines: 2; Tolerance: 50%; Shielding: Unshielded; DC Resistance (DCR): 500mR; Test Frequency: 100MHz
J13 = MRT9P3.81SQ-04P: Through Hole 4p right angle DIP (MRT8P3.81-04P need); Maker: STELVIO
J14 J15 = A2-2PA-2.54DSA: Headers & Wire Housings 2P M PIN HEADER SR STRAIGHT TYPE GOLD; Maker: HIROSE
R37-R42 = R [1608]_J: SMD  Chip Resistor +/-5% 1608(mm)
U17 U19 = ISO1044BD: CAN Interface IC Isolated CAN FD transceiver in small package 8-SOIC -40 to 125; Maker: Texas Instruments
U18 U20 = MCP2518FDT-H/SL: CAN Interface IC Stand-alone Low Power CAN FD Controller s/SPI Interface Grade 0; Maker: MIcrochip
Y3 Y4 = ECS-400-20-30B-DU-TR: Crystal 40MHz ±30ppm (Tol) ±100ppm (Stability) 20pF FUND 100Ohm 4-Pin Mini-SMD T/R; Maker: ECS

## Sheet 9_RS485.SchDoc
size A3; SheetNumber: 8; SheetTotal: 9; Organization: Altium Limited; Address1: L3, 12a Rodborough Rd; Address2: Frenchs Forest; Address3: NSW; Address4: Australia 2086
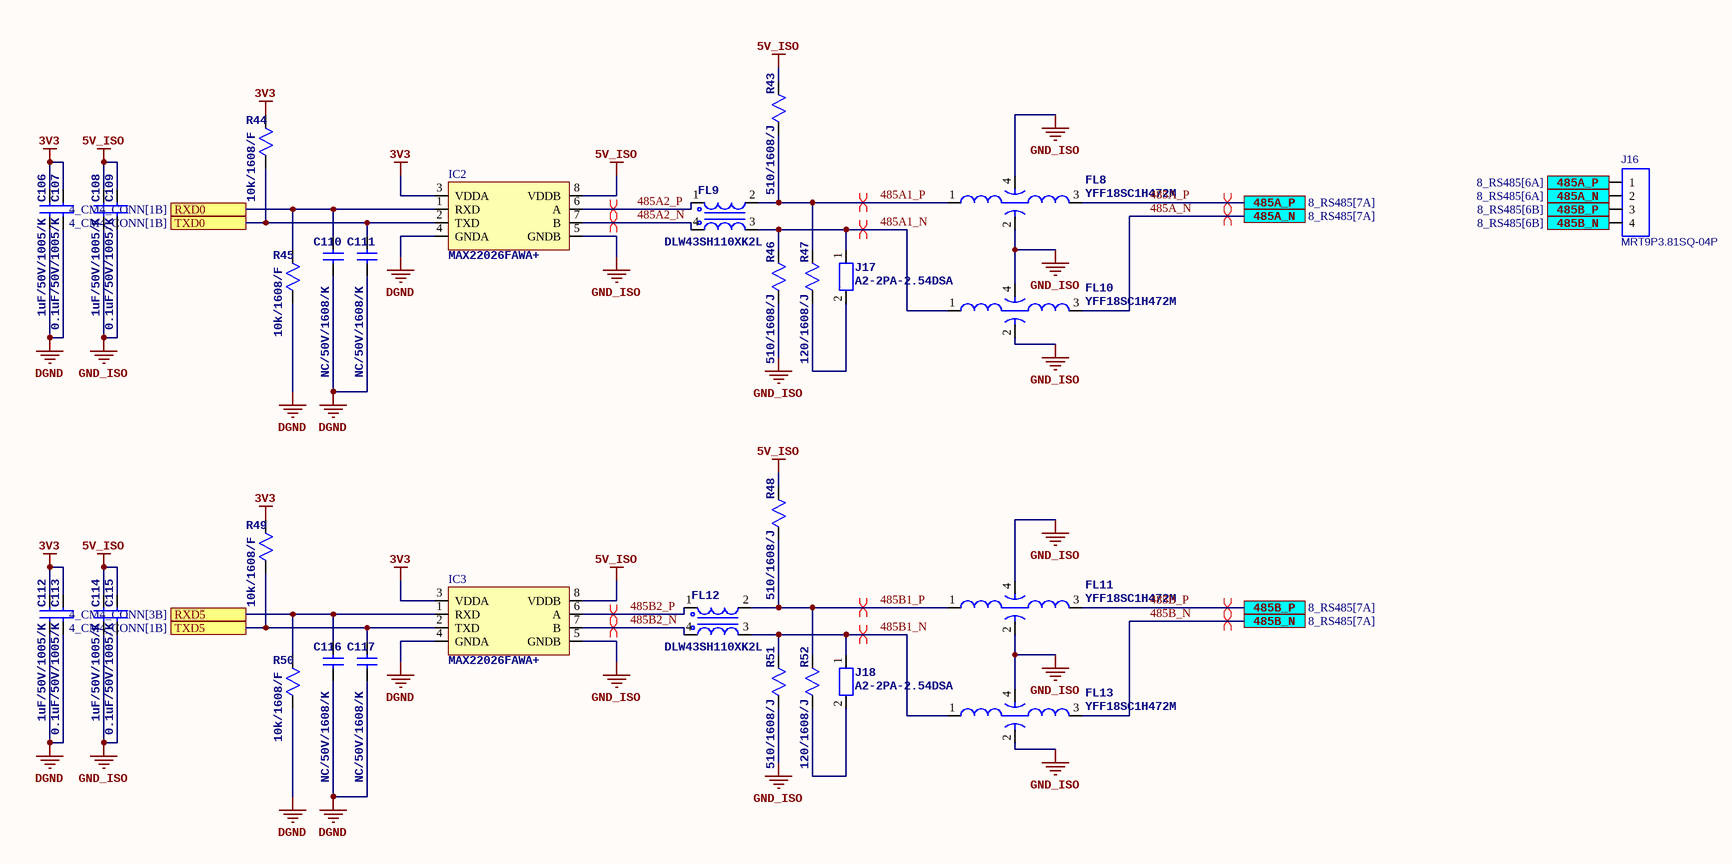
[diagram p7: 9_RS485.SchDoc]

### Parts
C106  value 1uF/50V/1005/K  [C1005]  (hidden comment: C [1005])
C107  value 0.1uF/50V/1005/K  [C1005]  (hidden comment: C [1005])
C108  value 1uF/50V/1005/K  [C1005]  (hidden comment: C [1005])
C109  value 0.1uF/50V/1005/K  [C1005]  (hidden comment: C [1005])
C110  value NC/50V/1608/K  [C1608]  (hidden comment: C [1608])
C111  value NC/50V/1608/K  [C1608]  (hidden comment: C [1608])
C112  value 1uF/50V/1005/K  [C1005]  (hidden comment: C [1005])
C113  value 0.1uF/50V/1005/K  [C1005]  (hidden comment: C [1005])
C114  value 1uF/50V/1005/K  [C1005]  (hidden comment: C [1005])
C115  value 0.1uF/50V/1005/K  [C1005]  (hidden comment: C [1005])
C116  value NC/50V/1608/K  [C1608]  (hidden comment: C [1608])
C117  value NC/50V/1608/K  [C1608]  (hidden comment: C [1608])
FL8  YFF18SC1H472M  [YFF18SC1H472M]
FL9  DLW43SH110XK2L  [DLW43SH110XK2L]
FL10  YFF18SC1H472M  [YFF18SC1H472M]
FL11  YFF18SC1H472M  [YFF18SC1H472M]
FL12  DLW43SH110XK2L  [DLW43SH110XK2L]
FL13  YFF18SC1H472M  [YFF18SC1H472M]
IC2  MAX22026FAWA+  [SOIC8-1.27_7.9]
IC3  MAX22026FAWA+  [SOIC8-1.27_7.9]
J16  MRT9P3.81SQ-04P  [MRT9P3.81SQ-04P]
J17  A2-2PA-2.54DSA  [A2-2PA-2.54DSA]
J18  A2-2PA-2.54DSA  [A2-2PA-2.54DSA]
R43  value 510/1608/J  [R1608]  (hidden comment: R [1608]_J)
R44  value 10k/1608/F  [R1608]  (hidden comment: R [1608]_J)
R45  value 10k/1608/F  [R1608]  (hidden comment: R [1608]_J)
R46  value 510/1608/J  [R1608]  (hidden comment: R [1608]_J)
R47  value 120/1608/J  [R1608]  (hidden comment: R [1608]_J)
R48  value 510/1608/J  [R1608]  (hidden comment: R [1608]_J)
R49  value 10k/1608/F  [R1608]  (hidden comment: R [1608]_J)
R50  value 10k/1608/F  [R1608]  (hidden comment: R [1608]_J)
R51  value 510/1608/J  [R1608]  (hidden comment: R [1608]_J)
R52  value 120/1608/J  [R1608]  (hidden comment: R [1608]_J)

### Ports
485A_N (see 8_RS485[6A]), 485A_N (see 8_RS485[7A]), 485A_P (see 8_RS485[6A]), 485A_P (see 8_RS485[7A]), 485B_N (see 8_RS485[6B]), 485B_N (see 8_RS485[7A]), 485B_P (see 8_RS485[6B]), 485B_P (see 8_RS485[7A]), RXD0 (see 4_CM4_CONN[1B]), RXD5 (see 4_CM4_CONN[3B]), TXD0 (see 4_CM4_CONN[1B]), TXD5 (see 4_CM4_CONN[1B])

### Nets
3V3: C106.1 C107.1 C112.1 C113.1 IC2.3(VDDA) IC3.3(VDDA) R44.1 R49.1
5V_ISO: C108.1 C109.1 C114.1 C115.1 IC2.8(VDDB) IC3.8(VDDB) R43.2 R48.2
DGND: C106.2 C107.2 C110.2 C111.2 C112.2 C113.2 C116.2 C117.2 IC2.4(GNDA) IC3.4(GNDA) R45.2 R50.2
GND_ISO: C108.2 C109.2 C114.2 C115.2 FL8.2(GND_1) FL8.4(GND_2) FL10.2(GND_1) FL10.4(GND_2) FL11.2(GND_1) FL11.4(GND_2) FL13.2(GND_1) FL13.4(GND_2) IC2.5(GNDB) IC3.5(GNDB) R46.1 R51.1
485A1_N: FL9.3 FL10.1(IN/OUT) J17.1 R46.2
485A1_P: FL8.1(IN/OUT) FL9.2 R43.1 R47.2
485A2_N: FL9.4 IC2.7(B)
485A2_P: FL9.1 IC2.6(A)
485A_N: FL10.3(OUT/IN) J16.2 ; port 485A_N
485A_P: FL8.3(OUT/IN) J16.1 ; port 485A_P
485B1_N: FL12.3 FL13.1(IN/OUT) J18.1 R51.2
485B1_P: FL11.1(IN/OUT) FL12.2 R48.1 R52.2
485B2_N: FL12.4 IC3.7(B)
485B2_P: FL12.1 IC3.6(A)
485B_N: FL13.3(OUT/IN) J16.4 ; port 485B_N
485B_P: FL11.3(OUT/IN) J16.3 ; port 485B_P
RXD0: C110.1 IC2.1(RXD) R45.1 ; port RXD0
RXD5: C116.1 IC3.1(RXD) R50.1 ; port RXD5
TXD0: C111.1 IC2.2(TXD) R44.2 ; port TXD0
TXD5: C117.1 IC3.2(TXD) R49.2 ; port TXD5
NetJ17_2: J17.2 R47.1
NetJ18_2: J18.2 R52.1

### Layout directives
differential pair: 485A1_N, 485A1_P, 485A2_N, 485A2_P, 485A_N, 485A_P, 485B1_N, 485B1_P, 485B2_N, 485B2_P, 485B_N, 485B_P

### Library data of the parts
C106-C109 C112-C115 = C [1005]: MLCC - SMD/SMT 50V X5R +/-10% 1005(mm)
C110 C111 C116 C117 = C [1608]: MLCC - SMD/SMT 50V X5R +/-10% 1608(mm)
FL8 FL10 FL11 FL13 = YFF18SC1H222M: as FL2 on sheet 8_CANFD
FL9 FL12 = DLW43SH110XK2L: as FL3 on sheet 8_CANFD
IC2 IC3 = MAX22026FAWA+: RS422/RS485 Transceiver, -40 to 85DEG C Rohs Compliant: Yes; Manufacturer: Maxim; PartNo.: MAX22026AWA+
J16 = MRT9P3.81SQ-04P: as J13 on sheet 8_CANFD
J17 J18 = A2-2PA-2.54DSA: as J14 on sheet 8_CANFD
R43-R52 = R [1608]_J: SMD  Chip Resistor +/-5% 1608(mm)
